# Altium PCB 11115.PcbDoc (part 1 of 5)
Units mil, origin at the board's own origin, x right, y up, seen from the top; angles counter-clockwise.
Board outline 4800 x 3500.1 mil, 4 copper layers (Top Layer, Layer 2, Layer 3, Bottom Layer), stack 61.6 mil thick; 316 components, 224 nets, 954 pads, 623 vias.
Unrouted connection lines stored in the file: 268.
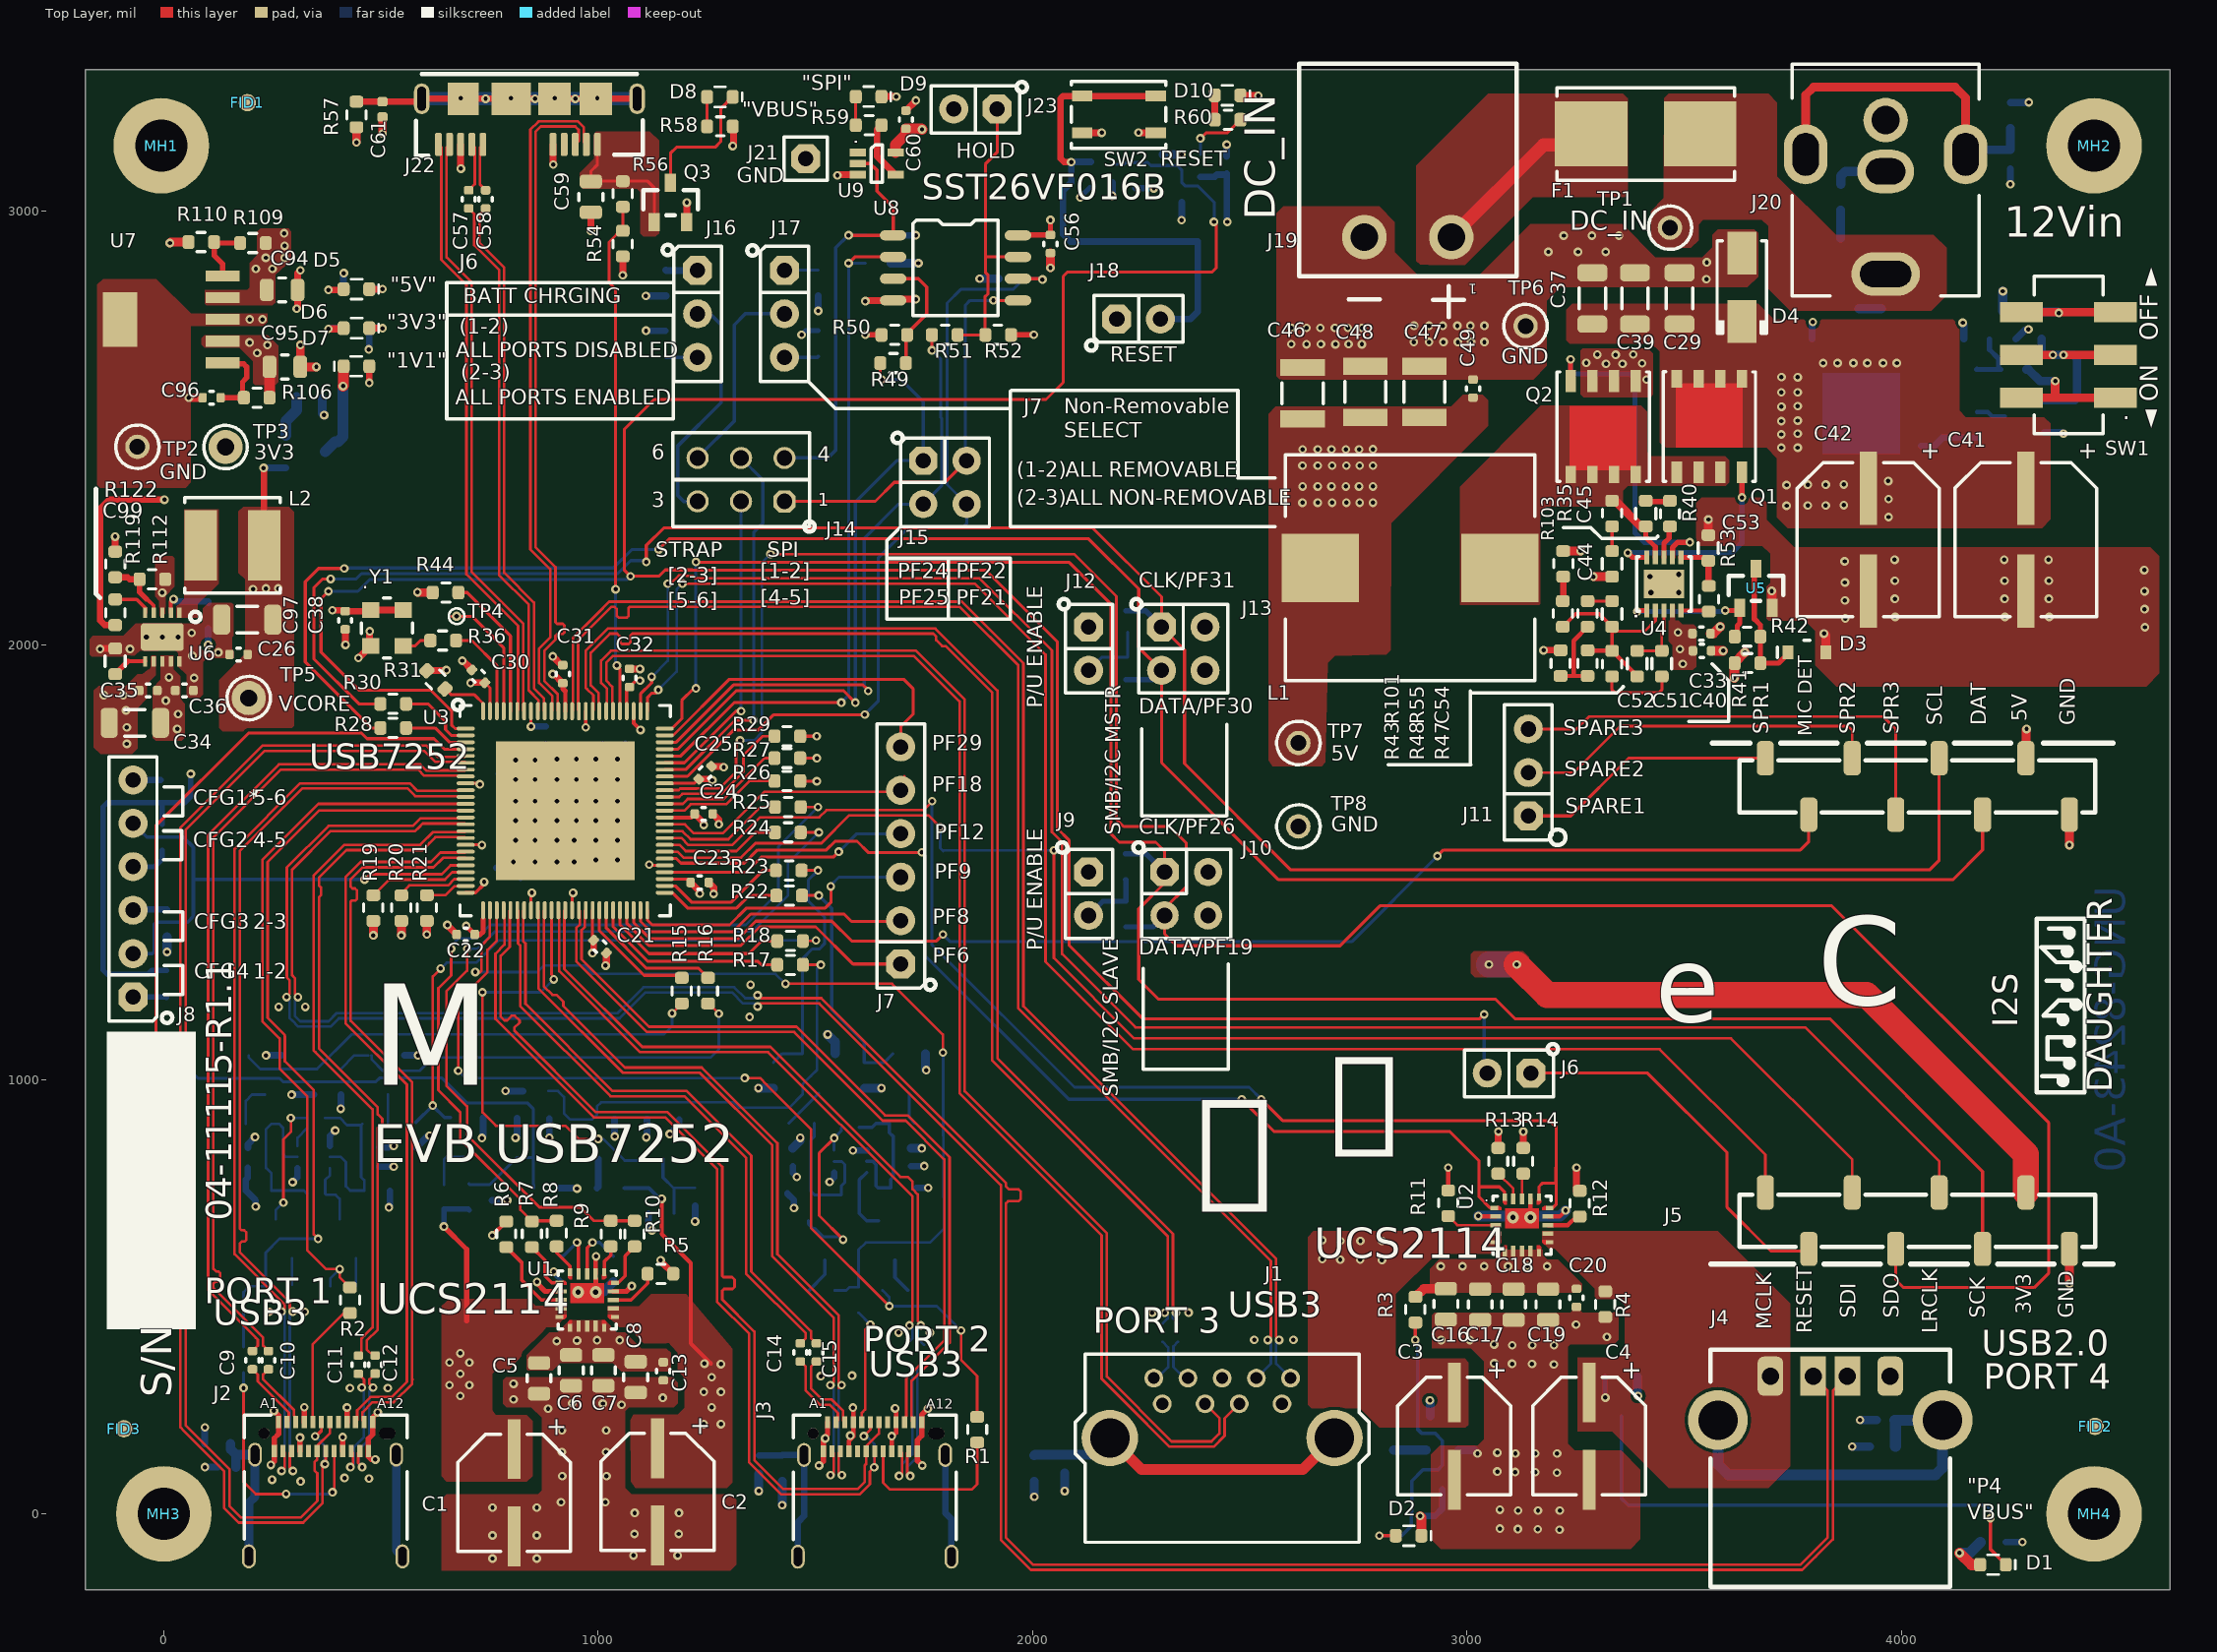
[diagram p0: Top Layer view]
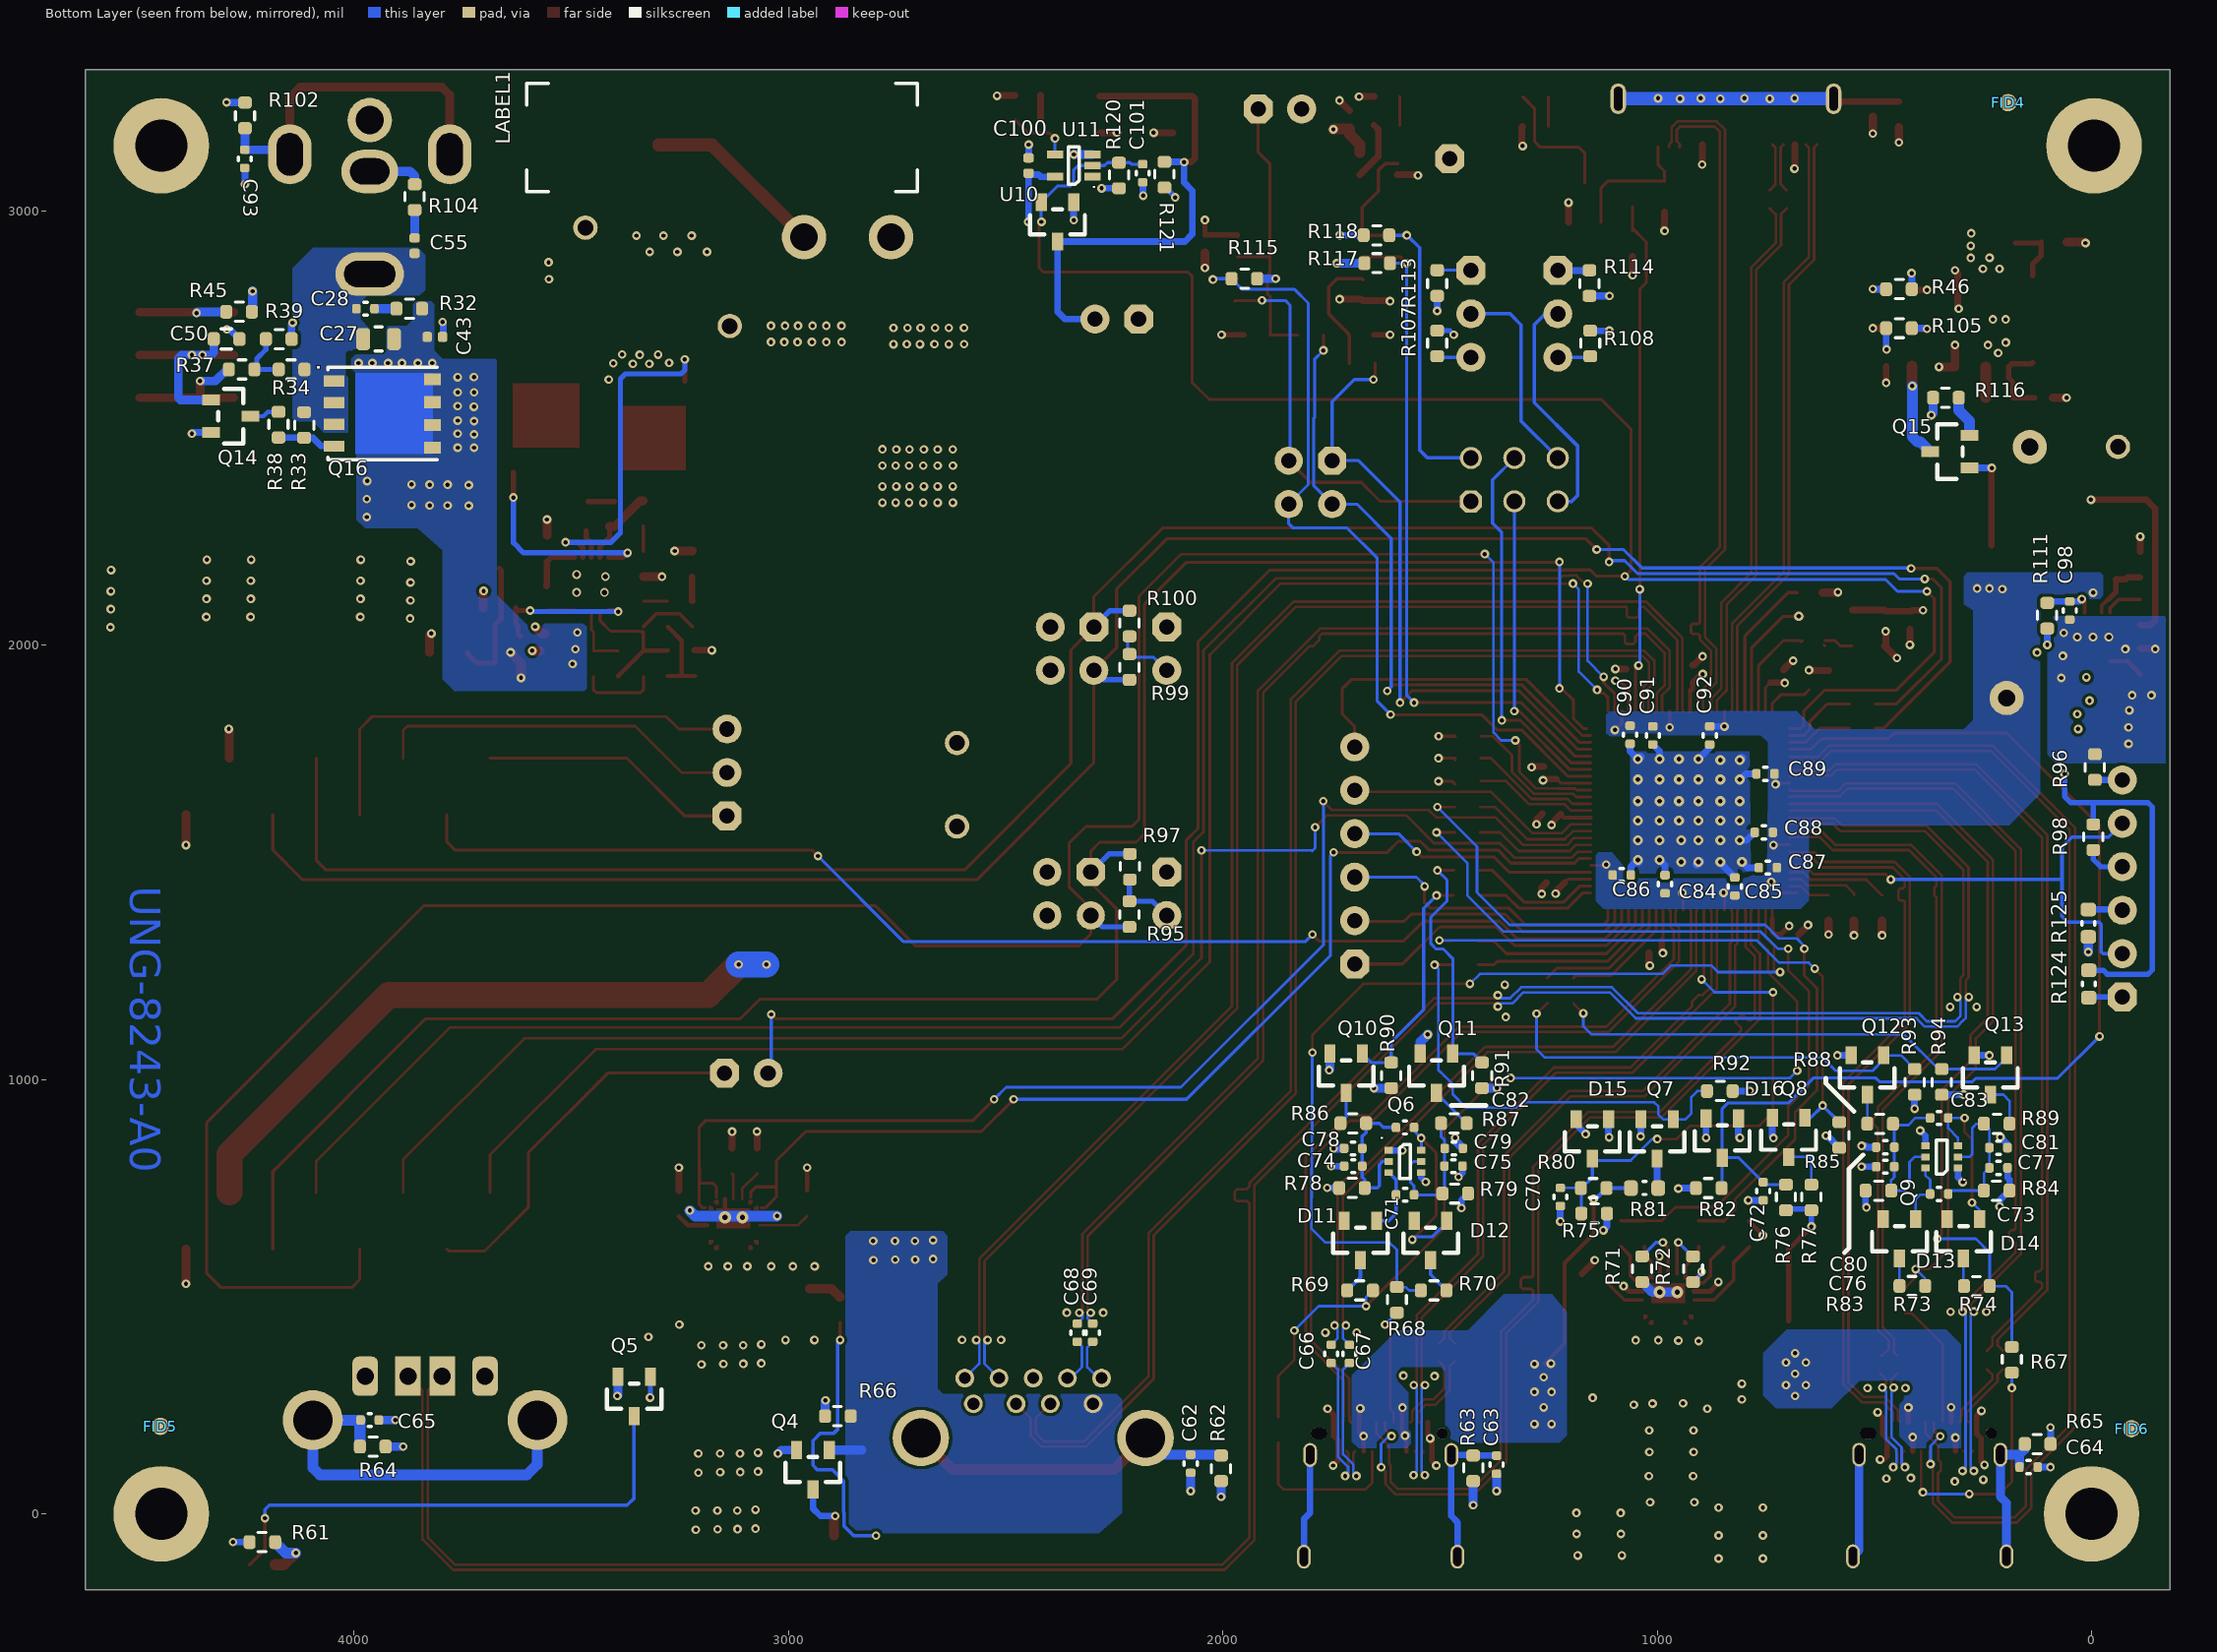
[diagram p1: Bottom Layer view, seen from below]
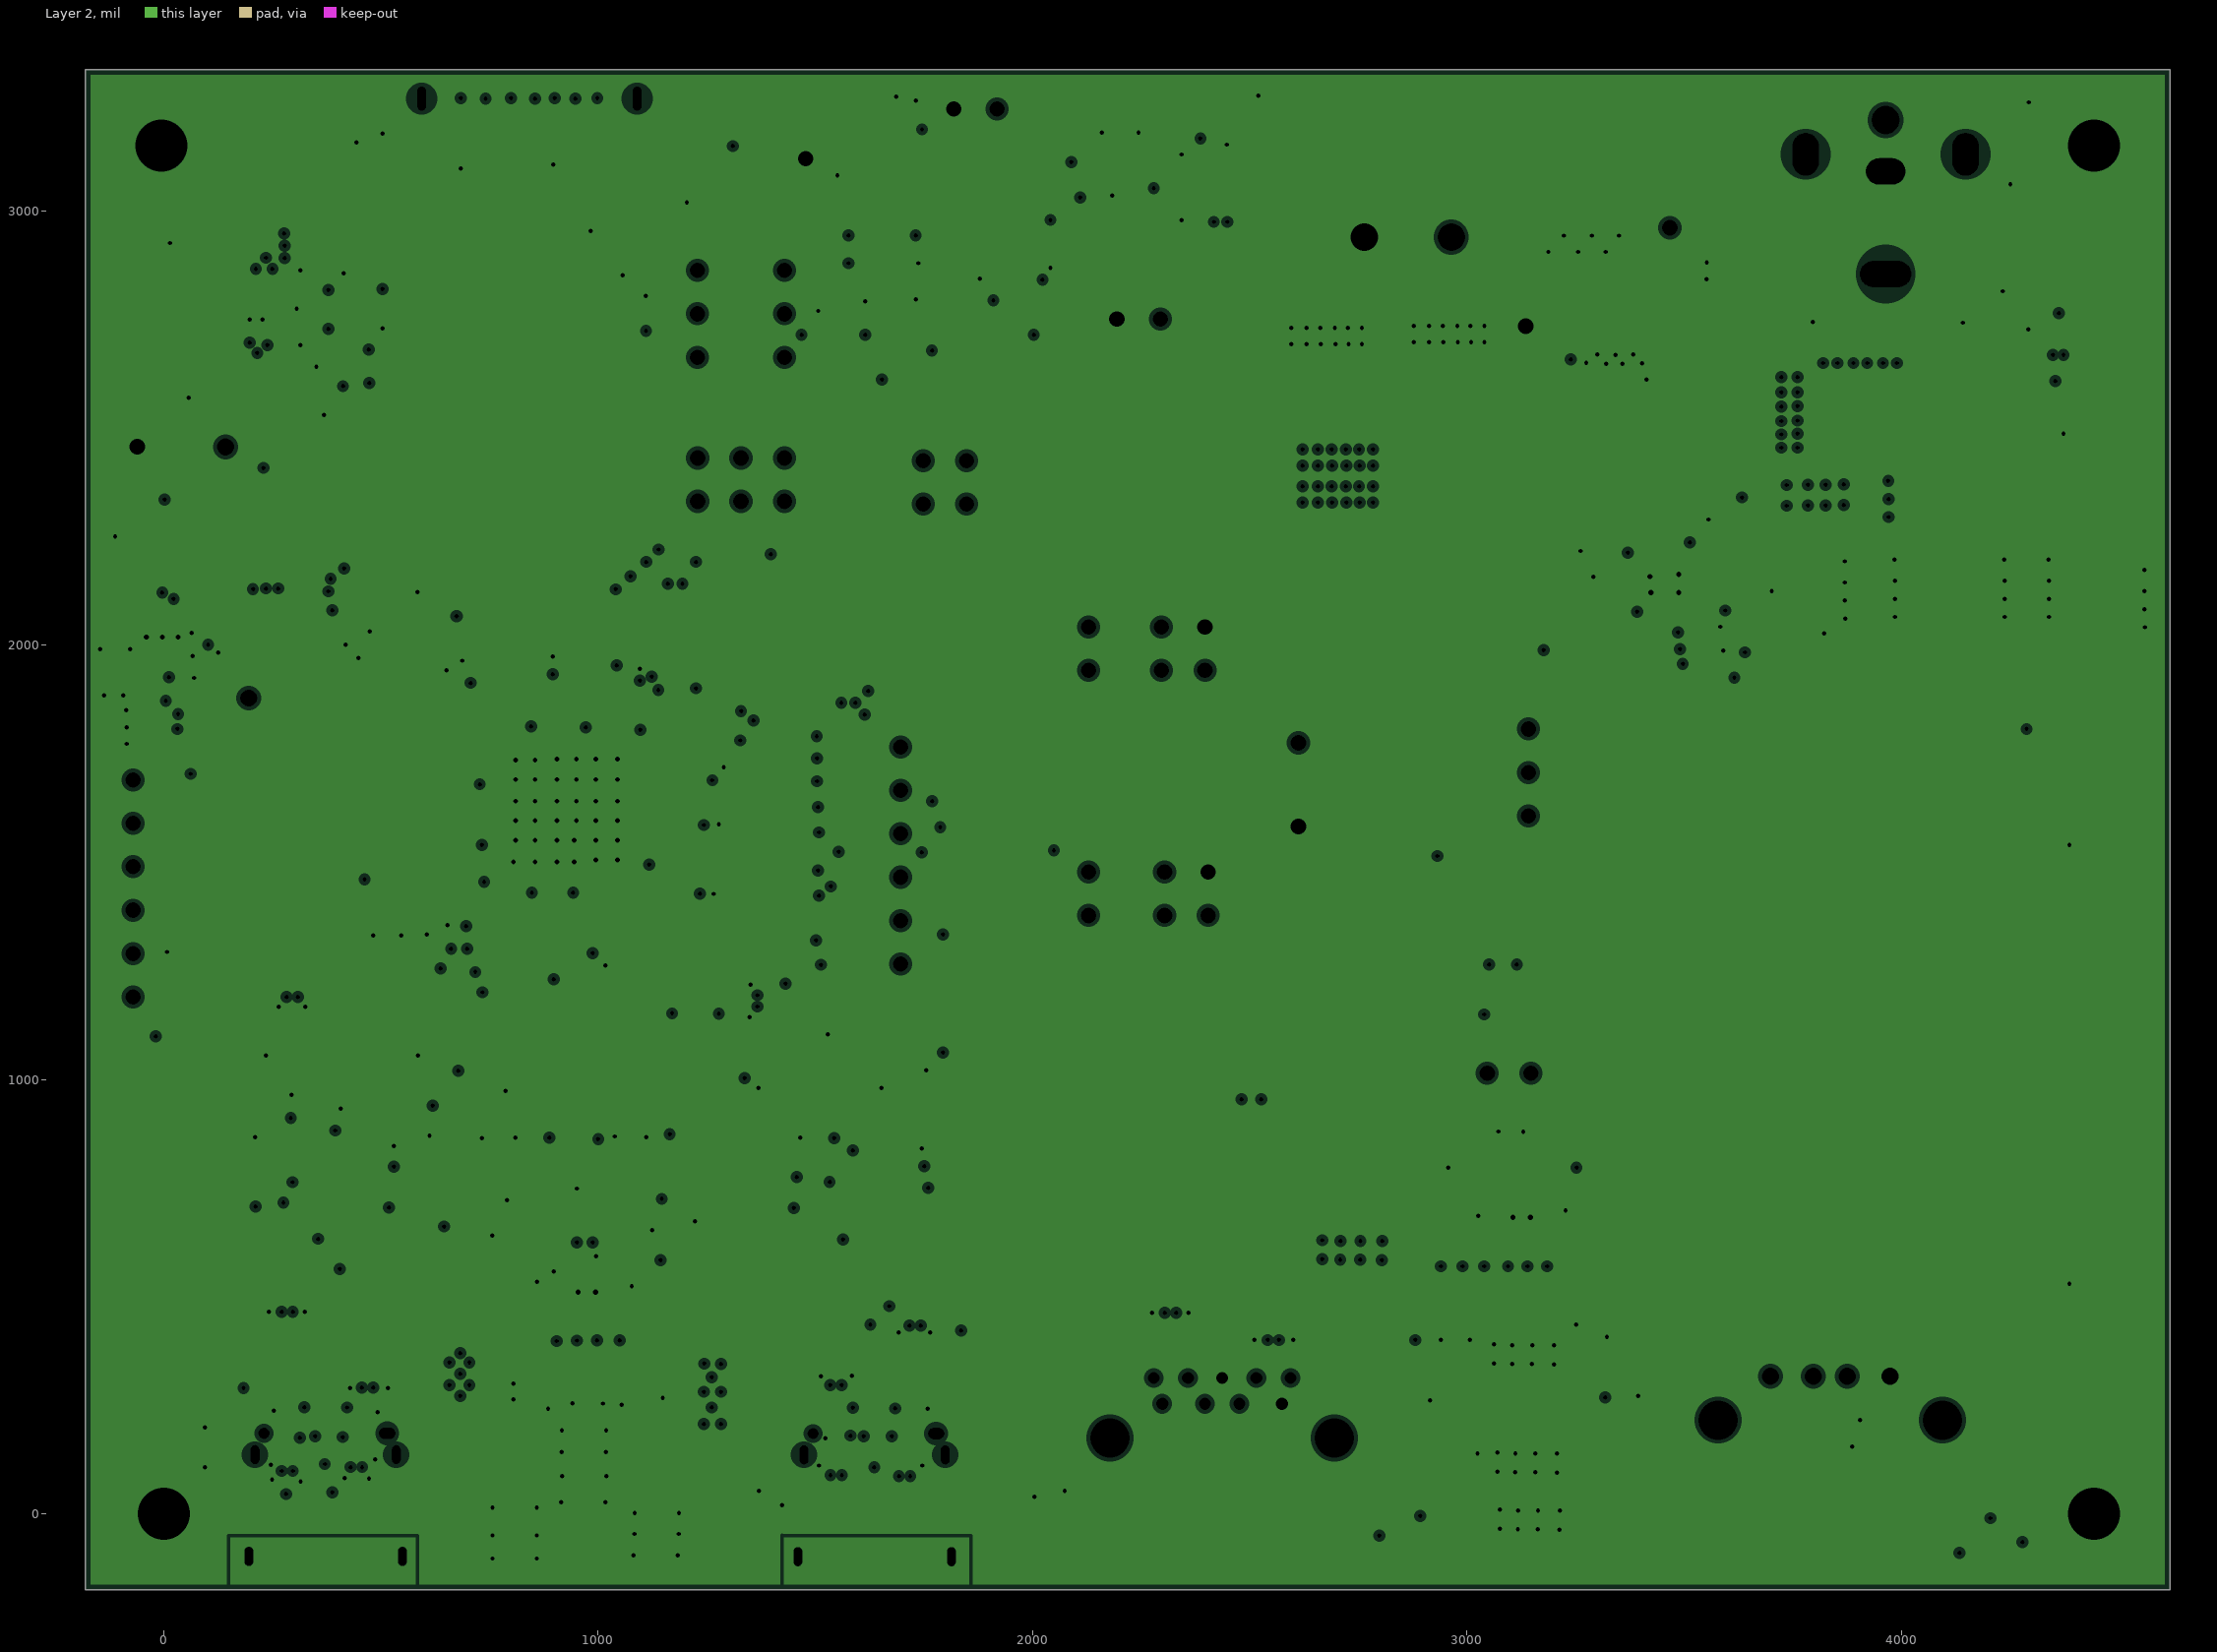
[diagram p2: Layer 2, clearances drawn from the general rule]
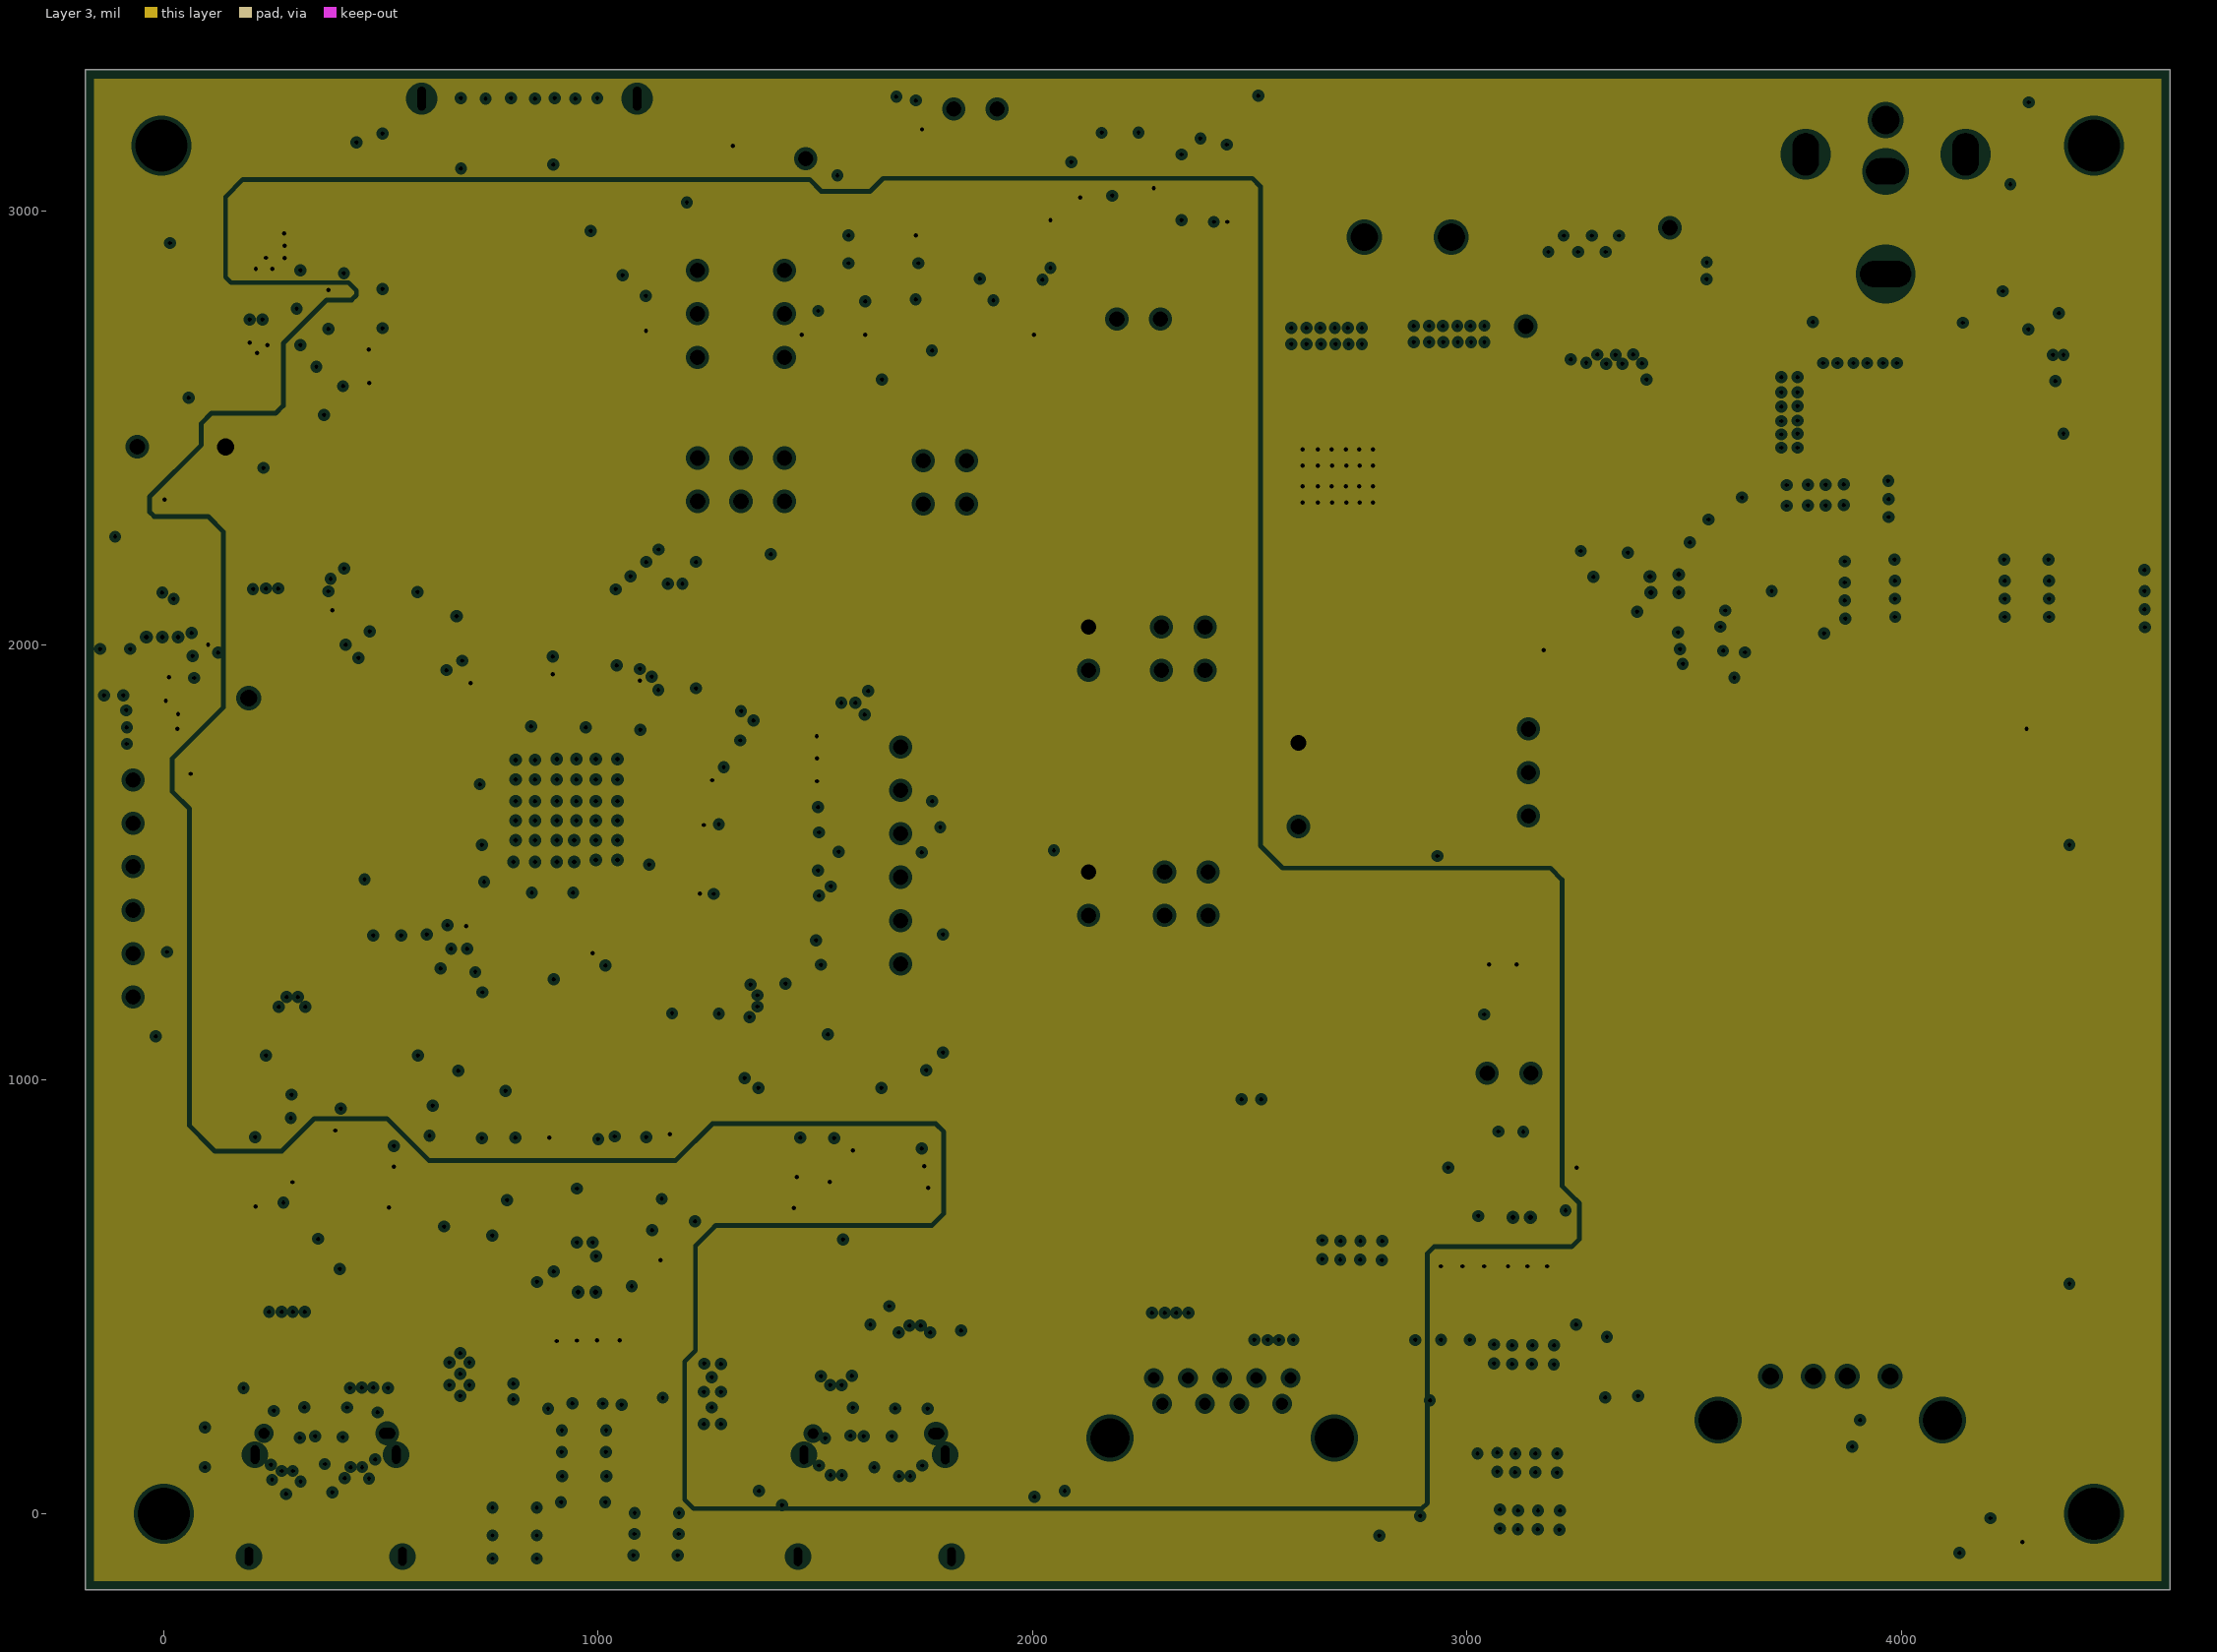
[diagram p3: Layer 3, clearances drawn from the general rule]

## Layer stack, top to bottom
Top Solder: solder mask 0.4, Solder Resist, Dk 3.5
Top Layer: signal copper 1.4
Dielectric 1: prepreg 4.5, 370HR(1PLY 1080&1PLY 106), Dk 4.2
Layer 2: plane copper 1.4, net (Multiple Nets)
Dielectric 2: core 47, 370 HR, Dk 4.3
Layer 3: plane copper 1.4, net (Multiple Nets)
Dielectric 3: dielectric 4.5, 370HR(1PLY 1080&1PLY 106), Dk 4.8
Bottom Layer: signal copper 1.4
Bottom Solder: solder mask 0.394, Solder Resist, Dk 3.5

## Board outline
-180.85,-175 4619.15,-175 4619.15,3325 -180.85,3325 -180.85,3325.1

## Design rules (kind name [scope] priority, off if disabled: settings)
AcuteAngle [All] p1: minimum=7.50000000000000E+0001 checktracksonly=TRUE
Clearance [All] p1: gap=6 ignorepadtopadclearanceinfootprint=TRUE except(5: Track-SMDPad; 7: THPad-Poly Via-Poly; 8: Arc-Poly Track-Poly SMDPad-Poly Fill-Poly; 12: Poly-Poly)
ComponentClearance ComponentClearance_ignore [HasFootprint('NET_TIE_0.5mm')] p1: gap=0 collisioncheckmode=3 verticalgap=0 showdistances=FALSE
ComponentClearance [All] p2: gap=7.87 collisioncheckmode=3 verticalgap=7.87 showdistances=FALSE
DiffPairsRouting [All] p1: maxlimit=7 minlimit=6 mostfreqgap=7 toplayer_minwidth=6 toplayer_maxwidth=6 toplayer_prefwidth=6 bottomlayer_minwidth=6 bottomlayer_maxwidth=6 bottomlayer_prefwidth=6 maxuncoupledlength=500
FabricationTestPointUsage TestPointUsage [All] p1: valid=0 allowmultiple=FALSE
FabricationTestpoint Testpoint [All] p1: side=3 testpointundercomponent=TRUE minsize=40 maxsize=100 preferedsize=60 minholesize=0 maxholesize=40 preferedholesize=32 testpointgrid=1 allowsidetop=TRUE allowsidebottom=TRUE usegrid=TRUE gridtolerance=0.01
HoleSize [All] p1: absolutevalues=TRUE maxlimit=236.22 minlimit=8 maxpercent=80.000 minpercent=20.000
HoleToHoleClearance [All] p1: gap=11.81 allowstackedmicrovias=FALSE
MinimumAnnularRing [All] p1: minimumring=3.9
MinimumSolderMaskSliver [All] p1: minsoldermaskwidth=1
PlaneClearance PlaneClearance_pads [IsPad] p1: clearance=8
PlaneClearance PlaneClearance_drill [All] p2: clearance=9
PlaneConnect usbcon [(HasFootprint('CON_USB3.1-C_RCPT_SMD_TH_RA_ACON') or InNet('GND1') or InNet('GND2'))] p1: planeconnectstyle=Direct reliefexpansion=20 reliefentries=4 reliefconductorwidth=10 reliefairgap=10
PlaneConnect PlaneConnect_full [IsVia] p2: planeconnectstyle=Direct reliefexpansion=19.68 reliefentries=4 reliefconductorwidth=11.81 reliefairgap=11.81
PlaneConnect [All] p3: planeconnectstyle=Relief reliefexpansion=10 reliefentries=4 reliefconductorwidth=15 reliefairgap=10
PolygonConnect PolygonConnect_full [All vs IsVia or IsNamedPolygon('full')] p1: connectstyle=Direct reliefconductorwidth=0 reliefentries=4 polygonreliefangle="90 Angle" airgapwidth=10
PolygonConnect [All] p2: connectstyle=Relief reliefconductorwidth=12 reliefentries=4 polygonreliefangle="90 Angle" airgapwidth=10
RoutingCorners [All] p1: cornerstyle=45-Degree minsetback=98.43 maxsetback=98.43
RoutingVias [All] p1: holewidth=10 width=20 viastyle="Through Hole" minholewidth=8 minwidth=18 maxholewidth=12 maxwidth=25
SMDToCorner [All] p1: distance=10000
ShortCircuit [IsNet] p1: allowed=FALSE
SilkToSilkClearance [All] p1: silktosilkclearance=3
SilkToSolderMaskClearance SilkscreenOverComponentPads [IsPad] p1: minsilkscreentomaskgap=0.1 clearancetoexposedcopper=TRUE
SolderMaskExpansion SolderMaskExpansion_Component_Via [IsComponentVia] p1: expansion=2.95 istentingtop=FALSE soldermaskfromhole=TRUE
SolderMaskExpansion [All] p2: expansion=3.94 istentingtop=FALSE
UnRoutedNet [All] p1: checkbadconnections=TRUE
ViasUnderSMD [All] p1: allowed=FALSE
Width [All] p1: maxlimit=200 minlimit=6 preferedwidth=7
16 further rules are at their usual default settings.

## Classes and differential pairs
component class 11115-6-Voltage_Regulators: C26 C27 C28 C29 C33 C34 C35 C36 C37 C39 C40 C41 C42 C43 C44 C45 C46 C47 C48 C49 C50 C51 C52 C53 C54 C55 C93 C94 C95 C96 C97 C98 C99 D3 D4 D5 D6 D7 F1 FID1 FID2 FID3 FID4 FID5 FID6 J19 J20 J21 L1 L2 LABEL1 MH1 MH2 MH3 MH4 Q1 Q2 Q14 Q15 Q16 R32 R33 R34 R35 R37 R38 R39 R40 R41 R42 R43 R45 R46 R47 R48 R53 R55 R101 R102 R103 R104 R105 R106 R109 R110 R111 R112 R116 R119 R122 SW1 TP1 TP2 TP3 TP5 TP6 TP7 TP8 U4 U5 U6 U7
component class "11115-5-USB-A Downstream 3-4": C3 C4 C16 C17 C18 C19 C20 C62 C65 C68 C69 D1 D2 J1 J4 Q4 Q5 R3 R4 R11 R12 R13 R14 R61 R62 R64 R66 U2
component class "11115-4-USB-C Downstream 1-2": C1 C2 C5 C6 C7 C8 C9 C10 C11 C12 C13 C14 C15 C63 C64 C66 C67 C70 C71 C72 C73 C74 C75 C76 C77 C78 C79 C80 C81 C82 C83 D11 D12 D13 D14 D15 D16 J2 J3 Q6 Q7 Q8 Q9 Q10 Q11 Q12 Q13 R1 R2 R5 R6 R7 R8 R9 R10 R63 R65 R67 R68 R69 R70 R71 R72 R73 R74 R75 R76 R77 R78 R79 R80 R81 R82 R83 R84 R85 R86 R87 R88 R89 R90 R91 R92 R93 R94 U1
component class 11115-3-USB-B-Upstream: C56 C57 C58 C59 C60 C61 D8 D9 J5 J6 J11 J15 J22 J23 Q3 R49 R50 R51 R52 R54 R56 R57 R58 R59 R115 R117 R118 U8 U9
component class 11115-2-USB7252: C21 C22 C23 C24 C25 C30 C31 C32 C38 C84 C85 C86 C87 C88 C89 C90 C91 C92 C100 C101 D10 J7 J8 J9 J10 J12 J13 J14 J16 J17 J18 R15 R16 R17 R18 R19 R20 R21 R22 R23 R24 R25 R26 R27 R28 R29 R30 R31 R36 R44 R60 R95 R96 R97 R98 R99 R100 R107 R108 R113 R114 R120 R121 R124 R125 SW2 TP4 U3 U10 U11 Y1
net class USB3.: C_USB3DN_TX3_N C_USB3DN_TX3_P C_USB3DN_TXD1A_N C_USB3DN_TXD1A_P C_USB3DN_TXD1B_N C_USB3DN_TXD1B_P C_USB3DN_TXD2A_N C_USB3DN_TXD2A_P C_USB3DN_TXD2B_N C_USB3DN_TXD2B_P UP_N UP_P USB2UP_N USB2UP_P USB3DN_RX1A_N USB3DN_RX1A_P USB3DN_RX1B_N USB3DN_RX1B_P USB3DN_RX2A_N USB3DN_RX2A_P USB3DN_RX2B_N USB3DN_RX2B_P USB3DN_RX3_N USB3DN_RX3_P USB3DN_TX1A_N USB3DN_TX1A_P USB3DN_TX1B_N USB3DN_TX1B_P USB3DN_TX2A_N USB3DN_TX2A_P USB3DN_TX2B_N USB3DN_TX2B_P USB3DN_TX3_N USB3DN_TX3_P USB3UP_RX_N USB3UP_RX_P USB3UP_TX_N USB3UP_TX_P
net class USB2.: USB2DN1/PRT_DIS_1_N USB2DN1/PRT_DIS_1_P USB2DN2/PRT_DIS_2_N USB2DN2/PRT_DIS_2_P USB2DN3/PRT_DIS_3_N USB2DN3/PRT_DIS_3_P USB2DN4/PRT_DIS_4_N USB2DN4/PRT_DIS_4_P USB2UP_N USB2UP_P
net class Power: 3V3_BRD 5V_BRD 5VL DC_IN EARTH_P0 EARTH_P1 EARTH_P2 EARTH_P3 EARTH_P4 FB3V3 FBVCORE GND L5V LVCORE VBUS1 VBUS3 VBUS4 VBUS_0 VCORE VIN
differential pair UP: +UP_P -UP_N
differential pair USB3UP_TX: +USB3UP_TX_P -USB3UP_TX_N
differential pair USB3UP_RX: +USB3UP_RX_P -USB3UP_RX_N
differential pair USB2UP: +USB2UP_P -USB2UP_N
differential pair USB3DN_TX3: +USB3DN_TX3_P -USB3DN_TX3_N
differential pair USB3DN_TX2B: +USB3DN_TX2B_P -USB3DN_TX2B_N
differential pair USB3DN_TX2A: +USB3DN_TX2A_P -USB3DN_TX2A_N
differential pair USB3DN_TX1B: +USB3DN_TX1B_P -USB3DN_TX1B_N
differential pair USB3DN_TX1A: +USB3DN_TX1A_P -USB3DN_TX1A_N
differential pair USB3DN_RX3: +USB3DN_RX3_P -USB3DN_RX3_N
differential pair USB3DN_RX2B: +USB3DN_RX2B_P -USB3DN_RX2B_N
differential pair USB3DN_RX2A: +USB3DN_RX2A_P -USB3DN_RX2A_N
differential pair USB3DN_RX1B: +USB3DN_RX1B_P -USB3DN_RX1B_N
differential pair USB3DN_RX1A: +USB3DN_RX1A_P -USB3DN_RX1A_N
differential pair USB2DN4/PRT_DIS_4: +USB2DN4/PRT_DIS_4_P -USB2DN4/PRT_DIS_4_N
differential pair USB2DN3/PRT_DIS_3: +USB2DN3/PRT_DIS_3_P -USB2DN3/PRT_DIS_3_N
differential pair USB2DN2/PRT_DIS_2: +USB2DN2/PRT_DIS_2_P -USB2DN2/PRT_DIS_2_N
differential pair USB2DN1/PRT_DIS_1: +USB2DN1/PRT_DIS_1_P -USB2DN1/PRT_DIS_1_N
differential pair C_USB3DN_TXD2B: +C_USB3DN_TXD2B_P -C_USB3DN_TXD2B_N
differential pair C_USB3DN_TXD2A: +C_USB3DN_TXD2A_P -C_USB3DN_TXD2A_N
differential pair C_USB3DN_TXD1B: +C_USB3DN_TXD1B_P -C_USB3DN_TXD1B_N
differential pair C_USB3DN_TXD1A: +C_USB3DN_TXD1A_P -C_USB3DN_TXD1A_N
differential pair C_USB3DN_TX3: +C_USB3DN_TX3_P -C_USB3DN_TX3_N

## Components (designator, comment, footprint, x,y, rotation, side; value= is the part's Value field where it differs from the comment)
C1 "Capacitor POL" CAP_AL_D8 806.5,48.7 r270 top value=150uF
C2 "Capacitor POL" CAP_AL_D8 1136.79,50.61 r270 top value=150uF
C3 "Capacitor POL" CAP_AL_D8 2970.85,179.08 r270 top value=150uF
C4 "Capacitor POL" CAP_AL_D8 3281.65,179.08 r270 top value=150uF
C5 "Capacitor NP" CAP_C_0805 863.94,312.07 r90 top value=47uF
C6 "Capacitor NP" CAP_C_0805 937.82,330.41 r270 top value=47uF
C7 "Capacitor NP" CAP_C_0805 1012.13,330.41 r90 top value=47uF
C8 "Capacitor NP" CAP_C_0805 1086.42,314.91 r270 top value=47uF
C9 "Capacitor NP" CAP_C_0402#1 204.2,353.98 r270 top value=0.1uF
C10 "Capacitor NP" CAP_C_0402#1 241.01,353.98 r270 top value=0.1uF
C11 "Capacitor NP" CAP_C_0402#1 447.94,343.44 r270 top value=0.1uF
C12 "Capacitor NP" CAP_C_0402#1 486.52,343.82 r270 top value=0.1uF
C13 "Capacitor NP" CAP_C_0402#1 1149.97,328.33 r90 top value=0.1uF
C14 "Capacitor NP" CAP_C_0402#1 1465.53,371.78 r270 top value=0.1uF
C15 "Capacitor NP" CAP_C_0402#1 1502.38,371.78 r270 top value=0.1uF
C16 "Capacitor NP" CAP_C_0805 2951.65,482.96 r90 top value=47uF
C17 "Capacitor NP" CAP_C_0805 3030.65,481.96 r270 top value=47uF
C18 "Capacitor NP" CAP_C_0805 3107.65,481.96 r270 top value=47uF
C19 "Capacitor NP" CAP_C_0805 3186.89,481.96 r90 top value=47uF
C20 "Capacitor NP" CAP_C_0402#1 3252.3,497.45 r90 top value=0.1uF
C21 "Capacitor NP" CAP_C_0402#1 1004.27,1306.11 r315 top value=0.1uF
C22 "Capacitor NP" CAP_C_0402#1 695.05,1334 r180 top value=0.1uF
C23 "Capacitor NP" CAP_C_0402#1 1233.92,1453.7 r0 top value=0.1uF
C24 "Capacitor NP" CAP_C_0402#1 1243.17,1611.74 r0 top value=0.1uF
C25 "Capacitor NP" CAP_C_0402#1 1246.37,1706.56 r45 top value=0.1uF
C26 "Capacitor NP" CAP_C_0402#1 172.22,1978.81 r0 top value=0.1uF
C27 "Capacitor NP" CAP_C_0805 3943.83,2705 r0 bottom value=10uF
C28 "Capacitor NP" CAP_C_0402#1 3974.15,2775 r180 bottom value=0.1uF
C29 "Capacitor NP" CAP_C_1206 3489.75,2798.52 r270 top value=10uF
C30 "Capacitor NP" CAP_C_0402#1 724.43,1928.55 r135 top value=0.1uF
C31 "Capacitor NP" CAP_C_0402#1 918.59,1933.5 r90 top value=0.1uF
C32 "Capacitor NP" CAP_C_0402#1 1072.15,1924.78 r90 top value=0.1uF
C33 "Capacitor NP" CAP_C_0402#1 3540.32,2026.88 r180 top value=0.1uF
C34 "Capacitor NP" CAP_C_1206 -66.55,1821.36 r0 top value=22uF
C35 "Capacitor NP" CAP_C_0402#1 -35.64,1895.97 r0 top value=0.1uF
C36 "Capacitor NP" CAP_C_0402#1 47.23,1895.97 r180 top value=0.1uF
C37 "Capacitor NP" CAP_C_1206 3288.82,2798.52 r270 top value=10uF
C38 "Capacitor NP" CAP_C_0402#1 417.75,2057.58 r90 top value=0.1uF
C39 "Capacitor NP" CAP_C_1206 3387,2798.52 r270 top value=10uF
C40 "Capacitor NP" CAP_C_0402#1 3541.32,1987.21 r180 top value=0.1uF
C41 "Capacitor POL" CAP_AL_F 4286.71,2243.11 r270 top value=47uF
C42 "Capacitor POL" CAP_AL_F 3924.15,2243.11 r270 top value=47uF
C43 "Capacitor NP" CAP_C_0402#2 3814,2710 r0 bottom value=0.1uF
C44 "Capacitor NP" CAP_C_0603 3334.21,2187.42 r270 top value=0.33uF
C45 "Capacitor NP" CAP_C_0603 3411.8,2303.24 r270 top value=0.33uF
C46 "Capacitor NP" CAP_C_1210 2622.02,2580.35 r270 top value=100uF
C47 "Capacitor NP" CAP_C_1210 2902.02,2583.3 r270 top value=100uF
C48 "Capacitor NP" CAP_C_1210 2766.2,2583.3 r270 top value=100uF
C49 "Capacitor NP" CAP_C_0402#1 3014.15,2590.96 r270 top value=0.1uF
C50 "Capacitor NP" CAP_C_0603 4293.72,2705 r0 bottom value=1uF
C51 "Capacitor NP" CAP_C_0603 3448.88,1957.68 r270 top value=3900pF
C52 "Capacitor NP" CAP_C_0603 3392.15,1957.68 r270 top value=33pF
C53 "Capacitor NP" CAP_C_0603 3556.07,2224.03 r270 top value=4.7uF
C54 "Capacitor NP" CAP_C_0603 3334.21,2072.16 r90 top value=680pF
C55 "Capacitor NP" CAP_C_0402#2 3860.8,2920.01 r270 bottom value=0.1uF
C56 "Capacitor NP" CAP_C_0402#1 2041.31,2923.95 r90 top value=0.1uF
C57 "Capacitor NP" CAP_C_0402#1 702,3026.78 r270 top value=0.1uF
C58 "Capacitor NP" CAP_C_0402#1 741,3026.65 r270 top value=0.1uF
C59 "Capacitor NP" CAP_C_0805 983.29,3032.36 r90 top value=10uF
C60 "Capacitor NP" CAP_C_0402#1 1708.58,3210 r90 top value=0.1uF
C61 "Capacitor NP" CAP_C_0402#2 503.5,3233.94 r90 top value=0.1uF
C62 "Capacitor NP" CAP_C_0402#1 2074.15,115.42 r90 bottom value=0.1uF
C63 "Capacitor NP" CAP_C_0402#1 1369.87,113.23 r90 bottom value=0.1uF
C64 "Capacitor NP" CAP_C_0402#1 145.02,107.76 r0 bottom value=0.1uF
C65 "Capacitor NP" CAP_C_0402#1 3964.15,216 r0 bottom value=0.1uF
C66 "Capacitor NP" CAP_C_0402#1 1750.73,368.37 r270 bottom value=0.1uF
C67 "Capacitor NP" CAP_C_0402#1 1708.65,368.23 r270 bottom value=0.1uF
C68 "Capacitor NP" CAP_C_0402#1 2335.17,417.36 r270 bottom value=0.1uF
C69 "Capacitor NP" CAP_C_0402#1 2299.72,417.36 r270 bottom value=0.1uF
C70 "Capacitor NP" CAP_C_0402#1 1223.18,729.67 r270 bottom value=0.1uF
C71 "Capacitor NP" CAP_C_0402#1 1580.75,734.66 r0 bottom value=0.1uF
C72 "Capacitor NP" CAP_C_0402#1 755.95,742.87 r270 bottom value=0.1uF
C73 "Capacitor NP" CAP_C_0402#1 350.95,736.73 r0 bottom value=0.1uF
C74 "Capacitor NP" CAP_C_0402#1 1699.88,800.8 r0 bottom value=0.1uF
C75 "Capacitor NP" CAP_C_0402#1 1469.18,800.8 r180 bottom value=0.1uF
C76 "Capacitor NP" CAP_C_0402#1 475.15,799.26 r0 bottom value=0.1uF
C77 "Capacitor NP" CAP_C_0402#1 214.51,796.73 r180 bottom value=0.1uF
C78 "Capacitor NP" CAP_C_0402#1 1699.88,841.57 r180 bottom value=0.1uF
C79 "Capacitor NP" CAP_C_0402#1 1468.39,841.57 r0 bottom value=0.1uF
C80 "Capacitor NP" CAP_C_0402#1 475.15,844.26 r180 bottom value=0.1uF
C81 "Capacitor NP" CAP_C_0402#1 214.51,843.13 r0 bottom value=0.1uF
C82 "Capacitor NP" CAP_C_0402#1 1580.75,889.73 r180 bottom value=0.1uF
C83 "Capacitor NP" CAP_C_0402#1 350.95,911.73 r180 bottom value=0.1uF
C84 "Capacitor NP" CAP_C_0402#1 982.05,1449.75 r90 bottom value=0.1uF
C85 "Capacitor NP" CAP_C_0402#1 821.41,1444.63 r90 bottom value=0.1uF
C86 "Capacitor NP" CAP_C_0402#1 1081.66,1470.96 r180 bottom value=0.1uF
C87 "Capacitor NP" CAP_C_0402#1 745.3,1487.89 r0 bottom value=0.1uF
C88 "Capacitor NP" CAP_C_0402#1 754.77,1569.14 r0 bottom value=0.1uF
C89 "Capacitor NP" CAP_C_0402#1 750.95,1703.98 r0 bottom value=0.1uF
C90 "Capacitor NP" CAP_C_0402#1 1062.45,1793.88 r270 bottom value=0.1uF
C91 "Capacitor NP" CAP_C_0402#1 1010.19,1792.36 r270 bottom value=0.1uF
C92 "Capacitor NP" CAP_C_0402#1 879.13,1792.36 r270 bottom value=0.1uF
C93 "Capacitor NP" CAP_C_0402#1 4252,3120 r270 bottom value=0.1uF
C94 "Capacitor NP" CAP_C_0805 272.51,2818.13 r180 top value=10uF
C95 "Capacitor NP" CAP_C_0805 278.84,2640.99 r180 top value=10uF
C96 "Capacitor NP" CAP_C_0402#1 110.1,2570 r0 top value=0.1uF
C97 "Capacitor NP" CAP_C_1206 192.23,2059.1 r0 top value=22uF
C98 "Capacitor NP" CAP_C_0402#1 50.23,2079.97 r90 bottom value=2.2uF
C99 "Capacitor NP" CAP_C_0603 -111.77,1963.06 r270 top value=470pF
C100 "Capacitor NP" CAP_C_0402#2 2447.45,3104.41 r90 bottom value=0.1uF
C101 "Capacitor NP" CAP_C_0402#1 2184.47,3086.69 r90 bottom value=0.1uF
D1 "LED_green" LED_0603_GREEN 4211.28,-117 r0 top value=GREEN
D2 "LED_green" LED_0603_GREEN 2865.9,-50.27 r0 top value=GREEN
D3 "Diode Zener" SOD-323 3782.85,1983.66 r180 top value=MM3Z5V1ST1G
D4 "Diode TVS Unidirectional" DO-214AC_SMA 3633.23,2824.57 r270 top value="15.3VWM 32.3VC"
D5 "LED_green" LED_0603_GREEN 443.5,2820 r0 top value=GREEN
D6 "LED_green" LED_0603_GREEN 443.5,2730 r0 top value=GREEN
D7 "LED_green" LED_0603_GREEN 443.5,2642.37 r180 top value=GREEN
D8 "LED_green" LED_0603_GREEN 1280.35,3262.64 r0 top value=GREEN
D9 "LED_blue" LED_0603_BLUE 1622.74,3263.18 r0 top value=BLUE
D10 "LED_red" LED_0603_RED 2449.15,3266.25 r0 top value=RED
D11 "Diode SBR160S23" SOT-23-3_REVERSED 1683.35,629.58 r0 bottom value=SBR160S23
D12 "Diode SBR160S23" SOT-23-3_REVERSED 1521.7,629.58 r0 bottom value=SBR160S23
D13 "Diode SBR160S23" SOT-23-3_REVERSED 442.34,633.31 r0 bottom value=SBR160S23
D14 "Diode SBR160S23" SOT-23-3_REVERSED 294.93,633.31 r0 bottom value=SBR160S23
D15 "Diode Dual AK" SOT-23-3 1149.39,863.17 r0 bottom value=BAV99
D16 "Diode Dual AK" SOT-23-3 850.44,865.31 r0 bottom value=BAV99
F1 "FUSE 2 pin" FUSEHOLDER_LITTLEFUSE_155900 3411.8,3177.24 r180 top value="FAST 10A"
FID1 "FIDUCIAL" FIDUCIAL 192.39,3249.35 r0 top
FID2 "FIDUCIAL" FIDUCIAL 4446.2,201.51 r0 top
FID3 "FIDUCIAL" FIDUCIAL -92,196.07 r0 top
FID4 "FIDUCIAL" FIDUCIAL 192.39,3249.4 r180 bottom
FID5 "FIDUCIAL" FIDUCIAL 4446.2,201.56 r180 bottom
FID6 "FIDUCIAL" FIDUCIAL -92,196.12 r180 bottom
J1 "CON USB3.0 A-B" CON_USB3.0-A_RCPT_TH_RA_WE_692121030100 2436.65,174.73 r0 top value="USB3.0 STD-A FEMALE"
J2 "USBC_Receptacle_SMD_RA" CON_USB3.1-C_RCPT_SMD_RA_ACP_12401610E4#2A 372.65,14.73 r0 top locked value="USB3.1 TYPE-C FEMALE"
J3 "USBC_Receptacle_SMD_RA" CON_USB3.1-C_RCPT_SMD_RA_ACP_12401610E4#2A 1636.65,14.08 r0 top value="USB3.1 TYPE-C FEMALE"
J4 "CON USB2.0 A-B" CON_USB2.0-A_TH_RA_FCI_87520-0010BLF 3836.65,216 r0 top value="USB2.0 STD-A FEMALE"
J5 "SOCKET I2S HOST" SOCKET_I2S_F_2.54_2x8_V_25.4x21_SMD 4037.22,1175 r90 top value="I2S HOST"
J6 "Header 1x2" HDR_M_2.54_1x2 3097.02,1015 r180 top value="HDR-2.54 Male 1x2"
J7 "Header 1x6" HDR_M_2.54_1x6 1696.66,1515.99 r90 top value="HDR-2.54 Male 1x6"
J8 "Header 1x6" HDR_M_2.54_1x6 -70.85,1440 r90 top value="HDR-2.54 Male 1x6"
J9 "Header 1x2" HDR_M_2.54_1x2 2129.15,1427.79 r270 top value="HDR-2.54 Male 1x2"
J10 "Header 2x2" HDR_M_2.54_2x2#1 2354.15,1427.79 r270 top value="HDR-2.54 Male 2x2"
J11 "Header 1x3" HDR_M_2.54_1x3 3141.41,1707.09 r90 top value="HDR-2.54 Male 1x3"
J12 "Header 1x2" HDR_M_2.54_1x2 2129.15,1992.28 r270 top value="HDR-2.54 Male 1x2"
J13 "Header 2x2" HDR_M_2.54_2x2#2 2347.14,1992.28 r270 top value="HDR-2.54 Male 2x2"
J14 "Header 3X2" CON_HDR_2.54_3X2 1328.96,2381.29 r90 top value="HDR-2.54 MALE 3X2"
J15 "Header 2x2" HDR_M_2.54_2x2#1 1798.52,2375 r270 top value="HDR-2.54 Male 2x2"
J16 "Header 1x3" HDR_M_2.54_1x3 1228.96,2763.13 r270 top value="HDR-2.54 Male 1x3"
J17 "Header 1x3" HDR_M_2.54_1x3 1428.96,2763.13 r270 top value="HDR-2.54 Male 1x3"
J18 "Header 1x2" HDR_M_2.54_1x2 2244.15,2750.87 r0 top value="HDR-2.54 Male 1x2"
J19 "Header 1x2" CON_TERMINAL_5.08_1x2_TH_RA_OST_OSTOQ025451 2864.15,2939.69 r180 top value="TERMINAL 1X2"
J20 "CON JACK 2C SHLD" CON_JACK_POWER_TH_RA_CUI_PJ-063BH 3964.15,3031.89 r90 top value="POWER 2.5mm"
J21 "Header 1x1" HDR_M_2.54_1x1 1477.85,3120.28 r0 top value="HDR-2.54 Male 1x1"
J22 "CON USB3.0 Micro B" CON_USB3.0-B_RCPT_SMD_RA_HIR_ZX360D-B-10P 856.15,3268.18 r180 top value="USB3.0 MICRO-B FEMALE"
J23 "Header 1x2" HDR_M_2.54_1x2 1868.69,3234.8 r180 top value="HDR-2.54 Male 1x2"
L1 "Inductor" IND_WE_7443551200_L12.8W12.8H6.2 2869.15,2178.28 r180 top value=2uH
L2 "Inductor" IND_MUR_LQH5B_L5W5H2 158.23,2229.97 r0 top value=1.5uH
LABEL1 "LABEL_Need_Help_Small" LABEL_Need_Help_Small 3153,3169 r0 bottom value="LABEL Need Help Small"
MH1 "MTHOLE 4-40 120DL 220PAD" MTHOLE_4-40#1 -5.85,3150 r0 top
MH2 "MTHOLE 4-40 120DL 220PAD" MTHOLE_4-40#1 4444.15,3150 r0 top
MH3 "MTHOLE 4-40 120DL 220PAD" MTHOLE_4-40#2 -5.85,0 r0 top
MH4 "MTHOLE 4-40 120DL 220PAD" MTHOLE_4-40#1 4444.15,0 r0 top
Q1 "Transistor MOS-N SSSGDDDD" Power56-8_5x6 3558.23,2503.36 r0 top value=SiRA24DP
Q2 "Transistor MOS-N SSSGDDDD" Power56-8_5x6 3313.82,2503.32 r180 top value=SiRA12BDP
Q3 "Transistor MOS-N GSD" SOT-23-3 1166.57,3019.32 r0 top value=2N7002-7-F
Q4 "Transistor MOS-N GSD" SOT-23-3 2943.85,101.79 r0 bottom value=2N7002-7-F
Q5 "Transistor MOS-N GSD" SOT-23-3 3355.4,270.45 r0 bottom value=2N7002-7-F
Q6 "Transistor MOS-P+P Dual SGDSGD" SC-88-6 1580.75,811.37 r270 bottom value=FDG6316P
Q7 "" SOT-23-3 1000.23,863.17 r0 bottom value=2N7002-7-F
Q8 "" SOT-23-3 697.38,867.01 r0 bottom value=2N7002-7-F
Q9 "Transistor MOS-P+P Dual SGDSGD" SC-88-6 345.15,821.73 r90 bottom value=FDG6316P
Q10 "" SOT-23-3 1716.34,1014.39 r0 bottom value=2N7002-7-F
Q11 "" SOT-23-3 1508.16,1014.39 r0 bottom value=2N7002-7-F
Q12 "" SOT-23-3 516.39,1010.49 r0 bottom value=2N7002-7-F
Q13 "" SOT-23-3 233.08,1010.49 r0 bottom value=2N7002-7-F
Q14 "Transistor MOS-N GSD" SOT-23-3 4283.87,2527.4 r270 bottom value=2N7002-7-F
Q15 "Transistor NPN BEC" SOT-23-3 326.38,2445.74 r90 bottom value=MMBT3904
Q16 "Transistor MOS-P SSSGDDDD" PG-TDSON-8_4.7x6.5 3934.82,2533.47 r270 bottom value="BSC060P03NS3E G"
R1 "0R" RES_C_0603#1 1872.65,193.68 r270 top
R2 "0R" RES_C_0603#1 428.68,491.75 r270 top
R3 "Resistor" RES_C_0603#1 2881.65,470 r270 top value=2.2k
R4 "Resistor" RES_C_0603#1 3318.76,482.92 r90 top value=1k
R5 "Resistor" RES_C_0603#1 1143.44,552.74 r180 top value=10k
R6 "Resistor" RES_C_0603#1 788.44,643.86 r270 top value=33k
R7 "Resistor" RES_C_0603#1 847.44,643.86 r270 top value=0R
R8 "Resistor" RES_C_0603#1 904.51,645.33 r270 top value=0R
R9 "Resistor" RES_C_0603#1 1029.08,645.33 r90 top value=0R
R10 "Resistor" RES_C_0603#1 1083.89,645.33 r90 top value=0R
R11 "Resistor" RES_C_0603#1 2957.13,715.2 r270 top value=33k
R12 "Resistor" RES_C_0603#1 3259.8,714.21 r270 top value=10k
R13 "100k" RES_C_0603#1 3072.22,812.96 r90 top
R14 "100k" RES_C_0603#1 3129.8,812.96 r90 top
R15 "0R" RES_C_0603#1 1192.54,1204.73 r90 top
R16 "0R" RES_C_0603#1 1253.06,1204.73 r90 top
R17 "0R" RES_C_0603#1 1441.75,1264.24 r180 top
R18 "0R" RES_C_0603#1 1441.75,1319.11 r180 top
R19 "Resistor" RES_C_0603#1 482.45,1394.86 r270 top value=200k
R20 "Resistor" RES_C_0603#1 546.95,1394.86 r270 top value=200k
R21 "Resistor" RES_C_0603#1 605.76,1394.86 r270 top value=10k
R22 "0R" RES_C_0603#1 1439.71,1423.77 r180 top
R23 "0R" RES_C_0603#1 1438.86,1481.64 r180 top
R24 "0R" RES_C_0603#1 1436.79,1569.14 r180 top
R25 "0R" RES_C_0603#1 1436.79,1627.49 r180 top
R26 "Resistor" RES_C_0603#1 1435.65,1687.42 r0 top value=10k
R27 "Resistor" RES_C_0603#1 1435.65,1740.16 r0 top value=10k
R28 "0R" RES_C_0603#1 528.3,1809.63 r0 top
R29 "Resistor" RES_C_0603#1 1435.65,1790.55 r0 top value=10k
R30 "0R" RES_C_0603#1 528.3,1865 r0 top
R31 "Resistor" RES_C_0603#1 626.51,1920.44 r315 top value=12k
R32 "20R" RES_C_0603#1 3873.2,2775 r0 bottom
R33 "Resistor" RES_C_0603#1 4115.13,2507.28 r90 bottom value=10k
R34 "Resistor" RES_C_0603#1 4144.15,2635 r180 bottom value=10k
R35 "Resistor" RES_C_0603#1 3334.21,2303.24 r270 top value=0R
R36 "Resistor" RES_C_0603#1 643.15,2010.83 r0 top value=0R
R37 "Resistor" RES_C_0603#1 4259.15,2635 r0 bottom value=470k
R38 "Resistor" RES_C_0603#1 4174.19,2507.72 r270 bottom value=2.2k
R39 "Resistor" RES_C_0603#1 4173.68,2705 r0 bottom value=20k
R40 "Resistor" RES_C_0603#1 3467.48,2303.24 r90 top value=0R
R41 "Resistor" RES_C_0603#1 3646.16,1958.86 r180 top value=10k
R42 "Resistor" RES_C_0603#1 3646.16,2019.8 r0 top value=10k
R43 "Resistor" RES_C_0603#1 3215.84,1958.86 r90 top value=0R
R44 "Resistor" RES_C_0603#1 648.65,2121.33 r180 top value=10k
R45 "Resistor" RES_C_0603#1 4265.06,2767.84 r0 bottom value=10k
R46 "Resistor" RES_C_0603#1 443.5,2820 r0 bottom value=2.2k
R47 "Resistor" RES_C_0603#1 3334.21,1957.68 r90 top value=8.2k
R48 "Resistor" RES_C_0603#1 3277.98,1958.86 r90 top value=20k
R49 "Resistor" RES_C_0603#1 1679.05,2649.73 r180 top value=0R
R50 "Resistor" RES_C_0603#1 1681.8,2714.67 r180 top value=10k
R51 "Resistor" RES_C_0603#1 1797.97,2714.67 r180 top value=0R
R52 "Resistor" RES_C_0603#1 1921.05,2714.67 r0 top value=10k
R53 "Resistor" RES_C_0603#1 3557.07,2107.03 r90 top value=100k
R54 "Resistor" RES_C_0603#1 1056.65,2924.73 r90 top value=49.9k
R55 "Resistor" RES_C_0603#1 3277.98,2072.16 r270 top value=750R
R56 "Resistor" RES_C_0603#1 1056.65,3038.91 r270 top value=43k
R57 "Resistor" RES_C_0603#1 443.5,3222.13 r90 top value=330R
R58 "Resistor" RES_C_0603#1 1280.35,3194.68 r180 top value=2.2k
R59 "Resistor" RES_C_0603#1 1622.74,3197.47 r180 top value=2.2k
R60 "Resistor" RES_C_0603#1 2449.15,3210 r180 top value=1k
R61 "Resistor" RES_C_0603#1 4211.28,-65 r180 bottom value=2.2k
R62 "Resistor" RES_C_0603#1 2004.15,105 r90 bottom value=330R
R63 "Resistor" RES_C_0603#1 1423.71,105 r270 bottom value=330R
R64 "Resistor" RES_C_0603#1 3957.22,155 r0 bottom value=330R
R65 "Resistor" RES_C_0603#1 124.15,160.9 r180 bottom value=330R
R66 "Resistor" RES_C_0603#1 2886.37,225.17 r180 bottom value=1k
R67 "0R" RES_C_0603#1 183.65,354.72 r270 bottom
R68 "0R" RES_C_0603#1 1599.46,492.7 r270 bottom
R69 "Resistor" RES_C_0603#1 1684.14,514.58 r180 bottom value=2R
R70 "Resistor" RES_C_0603#1 1514.85,514.58 r0 bottom value=2R
R71 "100k" RES_C_0603#1 1034.68,563.44 r270 bottom
R72 "100k" RES_C_0603#1 917.56,563.44 r270 bottom
R73 "Resistor" RES_C_0603#1 412.81,524.83 r180 bottom value=2R
R74 "Resistor" RES_C_0603#1 264.15,524.54 r180 bottom value=2R
R75 "Resistor" RES_C_0603#1 1145.2,691.52 r0 bottom value=49.9k
R76 "Resistor" RES_C_0603#1 703.65,728.55 r270 bottom value=43k
R77 "Resistor" RES_C_0603#1 644.91,728.57 r270 bottom value=560R
R78 "Resistor" RES_C_0603#1 1703.03,750.41 r0 bottom value=1k
R79 "Resistor" RES_C_0603#1 1465.17,737.54 r180 bottom value=1k
R80 "Resistor" RES_C_0603#1 1146.38,750.16 r180 bottom value=43k
R81 "Resistor" RES_C_0603#2 1029.19,750.16 r0 bottom value=560R
R82 "Resistor" RES_C_0603#1 881.38,750.16 r180 bottom value=49.9k
R83 "Resistor" RES_C_0603#1 490.9,744.31 r0 bottom value=1k
R84 "Resistor" RES_C_0603#1 218.47,744.31 r180 bottom value=1k
R85 "" RES_C_0603#1 580.95,872.39 r90 bottom value=100k
R86 "Resistor" RES_C_0603#1 1699.88,899.39 r180 bottom value=1k
R87 "Resistor" RES_C_0603#1 1468.39,899.39 r0 bottom value=1k
R88 "Resistor" RES_C_0603#1 486.86,898.31 r180 bottom value=1k
R89 "Resistor" RES_C_0603#1 218.47,898.31 r0 bottom value=1k
R90 "" RES_C_0603#1 1612.48,1009.86 r90 bottom value=100k
R91 "" RES_C_0603#1 1403.43,1009.86 r90 bottom value=100k
R92 "" RES_C_0603#1 855.94,973.67 r0 bottom value=100k
R93 "" RES_C_0603#1 407.44,994.74 r90 bottom value=100k
R94 "" RES_C_0603#1 345.15,994.74 r90 bottom value=100k
R95 "Resistor" RES_C_0603#1 2215,1381.04 r90 bottom value=10k
R96 "Resistor" RES_C_0603#1 -7.55,1719.53 r90 bottom value=200k
R97 "Resistor" RES_C_0603#1 2214.15,1490 r270 bottom value=10k
R98 "Resistor" RES_C_0603#1 -3.84,1558.02 r270 bottom value=200k
R99 "Resistor" RES_C_0603#1 2215,1950 r90 bottom value=10k
R100 "Resistor" RES_C_0603#1 2215,2050 r270 bottom value=10k
R101 "Resistor" RES_C_0603#1 3220.84,2072.16 r270 top value=2.55k
R102 "Resistor" RES_C_0603#1 4251.28,3220 r90 bottom value=330R
R103 "Resistor" RES_C_0603#1 3221.78,2187.42 r270 top value=0R
R104 "Resistor" RES_C_0603#1 3860.8,3031.89 r270 bottom value=20R
R105 "Resistor" RES_C_0603#1 443.5,2730 r0 bottom value=1k
R106 "Resistor" RES_C_0603#1 213.88,2570 r180 top value=10k
R107 "Resistor" RES_C_0603#1 1506.65,2694.73 r270 bottom value=10R
R108 "Resistor" RES_C_0603#1 1154.3,2694.73 r270 bottom value=10R
R109 "Resistor" RES_C_0603#1 205.31,2926.12 r0 top value=86.6k
R110 "Resistor" RES_C_0603#1 86.48,2928.32 r0 top value=12k
R111 "Resistor" RES_C_0603#1 102.23,2068 r270 bottom value=10k
R112 "Resistor" RES_C_0603#1 -26.17,2151.97 r0 top value=10k
R113 "Resistor" RES_C_0603#1 1506.65,2833.87 r90 bottom value=200k
R114 "Resistor" RES_C_0603#1 1156.06,2833.87 r90 bottom value=200k
R115 "Resistor" RES_C_0603#1 1950.58,2843.98 r0 bottom value=100k
R116 "Resistor" RES_C_0603#1 335.5,2570 r180 bottom value=500R
R117 "Resistor" RES_C_0603#1 1644.64,2879.73 r180 bottom value=100k
R118 "Resistor" RES_C_0603#1 1646.47,2943.98 r0 bottom value=10k
R119 "Resistor" RES_C_0603#1 -111.77,2185.97 r270 top value=12k
R120 "Resistor" RES_C_0603#1 2239.15,3081.72 r270 bottom value=100k
R121 "Resistor" RES_C_0603#1 2134.47,3083.54 r270 bottom value=300R
R122 "Resistor" RES_C_0603#1 -111.77,2075.97 r90 top value=10k
R124 "Resistor" RES_C_0603#2 6.64,1220 r270 bottom value=10k
R125 "Resistor" RES_C_0603#2 7.55,1360 r270 bottom value=10k
SW1 "Switch 6 Pin DPDT" SW_SLIDE_SMD_JS202011SCQN 4385.34,2668.38 r180 top value=JS202011SCQN
SW2 "Switch 4 Pin" SW_TACT_SMD_CK_PTS810SJM 2199.15,3222.28 r180 top value=SPST-NO
TP1 "Test Point" CON_TP_TH_V_RED_KEC_5000 3467.61,2961.42 r180 top value=Red
TP2 "Test Point" CON_TP_TH_V_BLK_KEC_5001 -60.78,2456.98 r270 top value="TP LOOP Black"
TP3 "Test Point" CON_TP_TH_V_ORN_KEC_5003 142.18,2456.34 r270 top value="TP LOOP Orange"
TP4 "Test Point No BOM" CON_TP_22P11_TH 674.18,2066.78 r90 top value="TP PAD .56mm"
TP5 "Test Point" CON_TP_TH_V_YEL_KEC_5004 195.68,1878.42 r0 top value="TP LOOP Yellow"
TP6 "Test Point" CON_TP_TH_V_BLK_KEC_5001 3135.15,2735 r0 top value=Black
TP7 "Test Point" CON_TP_TH_V_RED_KEC_5000 2612.18,1775 r0 top value="TP LOOP Red"
TP8 "Test Point" CON_TP_TH_V_BLK_KEC_5001 2612.18,1582.79 r0 top value=Black
U1 "UCS2114 VQFN-20" QFN-20_3X3_P0.5_EP0_UCS2114 974.64,492.69 r0 top value=UCS2114-1A
U2 "UCS2114 VQFN-20" QFN-20_3X3_P0.5_EP0_UCS2114 3126.65,665 r0 top value=UCS2114-1A
U3 "USB7252 VQFN-100" TQFN-100_12x12_EP8.0 924.18,1619.13 r0 top value=USB7252
U4 "MCP19035 DFN-10" DFN-10_3x3 3453.7,2141.06 r90 top locked value=MCP19035
U5 "MCP111_2 SOT-23-3_SC-70-3" SOT-23-3 3665.84,2131.21 r0 top value=MCP111/4.6V
U6 "MIC23201 MLF-10" MLF-10_3x3_1.6X2.5 -3.4,2018.97 r270 top value=MIC23201
U7 "MCP1825T_ADJE SOT-223" SOT-223-5 17.56,2750.34 r90 top value=MCP1825/ADJ
U8 "SST26VFXXX SOIC-8_WSON-8_SOIJ-8" SOIJ-8 1822.75,2868.98 r0 top value=SST26VF016B
U9 "74LVC1G14GW,125" SC-70-5 1641.65,3109.13 r270 top
U10 "MIC803 SOT-23-3" SOT-23-3 2380.77,2974.72 r0 bottom value=MIC803/2.93V
U11 "74LVC1G14GW,125" SC-70-5 2343.37,3104.41 r90 bottom
Y1 "OSCILLATOR_4P_nSTBY" OSCILLATOR_CDFN_L2.5W2.0H0.85 513.95,2039.73 r270 top value=25MHz

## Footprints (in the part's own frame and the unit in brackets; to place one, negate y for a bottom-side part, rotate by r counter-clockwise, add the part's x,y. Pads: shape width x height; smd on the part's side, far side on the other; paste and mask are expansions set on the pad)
CAP_AL_D8 [mm]
  rect 3.5x0.75 smd: 1(-2.55,0) 2(2.55,0)
  silkscreen extent -3.43,-3.3 3.43,3.3, body extent -3.5,-3.3 3.5,3.3, height 7.7
CAP_AL_F [mm]
  rect 4.3x1 smd: 1(-3,0) 2(3,0)
  silkscreen extent -4.5,-4.15 4.5,4.15, body extent -4.9,-4.15 5,4.15, height 10.2
CAP_C_0402#1 [mm] "Chip Capacitor 2-Leads, Body 1.6x0.8mm, IPC Medium Density"
  rrect50% 0.5x0.56 smd: 1(-0.53,0) 2(0.53,0)
  silkscreen extent -0.1,-0.38 0.1,0.38, body extent -0.5,-0.25 0.5,0.25, height 0.49
CAP_C_0402#2 [mm] "Chip Capacitor, 2-Leads, Body 1.0x0.5mm, IPC High Density"
  rrect50% 0.55x0.6 smd: 1(-0.45,0) 2(0.45,0)
  body extent -0.5,-0.3 0.5,0.3, height 0.2
CAP_C_0603 [mm] "Chip Capacitor 2-Leads, Body 1.6x0.8mm, IPC Medium Density"
  rrect50% 0.7x0.8 smd: 1(-0.75,0) 2(0.75,0)
  silkscreen extent -0.29,-0.58 0.3,0.58, body extent -0.8,-0.4 0.8,0.4, height 0.79
CAP_C_0805 [mm] "Chip Capacitor, 2-Leads, Body 2.0x1.3mm, IPC Medium Density"
  rrect50% 0.8x1.3 smd: 1(-0.9,0) 2(0.9,0)
  silkscreen extent -0.2,-0.7 0.2,0.7, body extent -1,-0.62 1,0.63, height 0.78
CAP_C_1206 [mm] "Chip Capacitor, 2-Leads, Body 3.2x1.6mm, IPC Medium Density"
  rrect50% 1x1.75 smd: 1(-1.5,0) 2(1.5,0)
  silkscreen extent -0.6,-0.77 0.6,0.77, body extent -1.6,-0.8 1.6,0.8, height 1
CAP_C_1210 [mm] "Chip Capacitor, 2-Leads, Body 3.2x2.5mm, IPC Medium Density"
  rect 1x2.6 smd: 1(-1.5,0) 2(1.5,0)
  silkscreen extent -0.6,-1.2 0.6,1.2, body extent -1.6,-1.25 1.6,1.25, height 0.95
CON_HDR_2.54_3X2 [mil] "Header Male Vertical Dual Row 3 Way 2.54mm Pitch"
  oct 51x51 hole 36: 1(-50,-100)
  round 51 hole 36: 2(-50,0) 3(-50,100) 4(50,-100) 5(50,0) 6(50,100)
  silkscreen extent -108,-157 108,157, body extent -100,-150 100,150, height 330
CON_JACK_POWER_TH_RA_CUI_PJ-063BH [mm] "Connector, Power Jack, 2.5mm x 6.5mm, 16V, 8A, Right Angle, TH"
  oval 3.516x2.54 hole 1.524 slot 2.5 at 0 deg: 0(2.5,4.677) 0(2.5,-4.677)
  oval 2.54x4 hole 1.524 slot 3 at 90 deg: 1(-4.5,0)
  oval 2.54x3.316 hole 1.524 slot 2.3 at 90 deg: 2(1.5,0)
  round 2.6 hole 1.663: ""(4.5,0)
  silkscreen extent -5.79,-5.46 7.77,5.46, body extent -5.51,-5.12 7.49,5.17, height 10
CON_TERMINAL_5.08_1x2_TH_RA_OST_OSTOQ025451 [mm] "TERMINAL BLOCK 5.08MM 2POS PCB RA"
  round 2.6 hole 1.6: 1(-2.54,0) 2(2.54,0)
  silkscreen extent -6.35,-10.15 6.35,2.29, body extent -6.1,-10 6.06,2, height 8.5
CON_TP_22P11_TH [mil]
  oval 22x22.05 hole 11 paste-22.05 mask+2: 1(0,0)
  silkscreen extent -18,-18 18,18
CON_TP_TH_V_BLK_KEC_5001 [mil] "TEST POINT PC MULTI PURPOSE MINI BLACK"
  round 56 hole 36: 1(0,0)
  silkscreen extent -50,-50 50,50, body extent -50,-50 50,50, height 192
CON_TP_TH_V_ORN_KEC_5003 [mm] "TEST POINT PC MULTI PURPOSE MINI ORN"
  round 2 hole 1: 1(0,0)
  silkscreen extent -1.27,-1.27 1.27,1.27, body extent -1.27,-1.27 1.27,1.27, height 4.89
CON_TP_TH_V_RED_KEC_5000 [mil] "TEST POINT PC MULTI PURPOSE MINI RED"
  round 56 hole 36: 1(0,0)
  silkscreen extent -50,-50 50,50, body extent -50,-50 50,50, height 192
CON_TP_TH_V_YEL_KEC_5004 [mm] "TEST POINT PC MULTI PURPOSE MINI YEL"
  round 2 hole 1: 1(0,0)
  silkscreen extent -1.27,-1.27 1.27,1.27, body extent -1.27,-1.27 1.27,1.27, height 4.89
CON_USB2.0-A_TH_RA_FCI_87520-0010BLF [mm] "CONN USB 2.0 A RCPT TH R/A L=14mm, W=13.1mm, H=7mm"
  round 3.5 hole 2.3: 0(-6.57,0) 0(6.57,0)
  rrect50% 1.5x2.3 hole 1: 1(-3.5,2.565) 4(3.5,2.565)
  rect 1.5x2.3 hole 1: 2(-1,2.565) 3(1,2.565)
  silkscreen extent -7,-9.75 7,4.13, body extent -7.9,-10.3 7.9,3.4, height 6.95
CON_USB3.0-A_RCPT_TH_RA_WE_692121030100 [mm]
  round 3.3 hole 2.3: 0(-6.57,0) 0(6.57,0)
  round 1.1 hole 0.7: 1(-3.5,2) 2(-1,2) 3(1,2) 4(3.5,2) 5(4,3.5) 6(2,3.5) 7(0,3.5) 8(-2,3.5) 9(-4,3.5)
  silkscreen extent -8.6,-6.1 8.6,4.9, body extent -7.74,-11.78 7.74,4.7, height 8.06
CON_USB3.0-B_RCPT_SMD_RA_HIR_ZX360D-B-10P [mm] "CONN RCPT USB 3.0 MICRO B SMD, L=12.85mm, W=5.0mm, H=2.5mm"
  oval 0.9x1.8 hole 0.5 slot 1.4 at 90 deg: 0(-5.935,0.25) 0(6.665,0.25)
  rect 1.9x1.9 smd: 0(-3.515,0.25) 0(-1.115,0.25)
  rect 2.3x1.9 smd: 0(1.435,0.25)
  rect 1.8x1.9 smd: 0(4.235,0.25)
  rrect50% 0.4x1.35 smd: 1(-3.615,2.925) 2(-2.965,2.925) 3(-2.315,2.925) 4(-1.665,2.925) 5(-1.015,2.925) 6(3.085,2.925) 7(3.735,2.925) 8(4.385,2.925) 9(5.035,2.925) 10(5.685,2.925)
  silkscreen extent -6.26,-1.2 6.99,3.58, body extent -6.42,-2.5 7.15,3.1, height 2.83
CON_USB3.1-C_RCPT_SMD_RA_ACP_12401610E4#2A [mm] "USB TYPE-C, RA RCPT, SMT"
  round 0.65 hole 0.65 unplated paste-0.325: 0(-3.6,4.34)
  oval 0.95x0.65 hole 0.65 slot 0.95 at 0 deg unplated paste-0.325: 0(3.6,4.34)
  oval 0.8x1.4 hole 0.5 slot 1.1 at 90 deg paste-1.4 mask+0: 25(-4.49,-2.86) 25(-4.13,3.09) 25(4.13,3.09) 25(4.49,-2.86)
  rect 0.3x0.7 smd mask+0: A1(-2.75,5) A2(-2.25,5) A3(-1.75,5) A4(-1.25,5) A5(-0.75,5) A6(-0.25,5) A7(0.25,5) A8(0.75,5) A9(1.25,5) A10(1.75,5) A11(2.25,5) A12(2.75,5) B1(2.5,3.3) B2(2,3.3) B3(1.5,3.3) B4(1,3.3) B5(0.5,3.3) B6(0,3.3) B7(-0.5,3.3) B8(-1,3.3) B9(-1.5,3.3) B10(-2,3.3) B11(-2.5,3.3) B12(-3,3.3)
  silkscreen extent -4.76,-1.86 4.77,5.41, body extent -4.6,-5.27 4.6,5.23, height 3.01
DFN-10_3x3 [mm] "DFN, 10-Leads, Body 3.0x3.0mm (max), Pitch 0.50mm, IPC Medium Density"
  rect 0.8x0.3 smd paste-0.038 mask+0.05: 1(-1.55,1) 2(-1.55,0.5) 3(-1.55,0) 4(-1.55,-0.5) 5(-1.55,-1) 6(1.55,-1) 7(1.55,-0.5) 8(1.55,0) 9(1.55,0.5) 10(1.55,1)
  rect 1.65x2.38 smd paste-0.305: 11(0,0)
  silkscreen extent -1.6,-1.6 1.6,1.6, body extent -1.56,-1.55 1.56,1.55, height 0.8
DO-214AC_SMA [mm] "Molded Diode, 2-Leads, Body 5.0x2.7mm, IPC Medium Density"
  rect 2.5x1.7 smd: 1(-2,0) 2(2,0)
  silkscreen extent -2.7,-1.5 2.7,1.5, body extent -2.6,-1.3 2.6,1.3, height 2.4
FIDUCIAL [mil]
  round 40 smd mask+20: 1(0,0)
  Top Layer pour cut-out: 40.35,0 38.97,10.44 34.94,20.17 28.53,28.53 20.17,34.94 10.44,38.97 0,40.35 0,40.35 -10.44,38.97 -20.17,34.94 -28.53,28.53 -34.94,20.17 -38.97,10.44 -40.35,0 -40.35,0 -38.97,-10.44 -34.94,-20.17 -28.53,-28.53 -20.17,-34.94 -10.44,-38.97 0,-40.35 0,-40.35 10.44,-38.97 20.17,-34.94 28.53,-28.53 34.94,-20.17 38.97,-10.44 40.35,0
  body extent -40,-40 40,40, height 0
FUSEHOLDER_LITTLEFUSE_155900 [mm] "FUSE BRD MNT WITH HOLDER LITTLEFUSE-154 SMD"
  rect 4.24x3.81 smd: 1(-3.19,0) 2(3.19,0)
  silkscreen extent -5.2,-2.7 5.2,2.7, body extent -4.86,-2.5 4.84,2.5, height 3.69
HDR_M_2.54_1x1 [mm] "Header Male Vertical 1 Way"
  oct 1.7x1.7 hole 0.9: 1(0,0)
  silkscreen extent -1.27,-1.27 1.27,1.27, body extent -1.27,-1.27 1.27,1.27, height 5.94
HDR_M_2.54_1x2 [mm] "Header Male Vertical 4 Way 2.54mm Pitch"
  oct 1.7x1.7 hole 0.9: 1(-1.27,0)
  round 1.7 hole 0.9: 2(1.27,0)
  silkscreen extent -2.6,-1.35 2.6,1.4, body extent -2.54,-1.27 2.54,1.27, height 5.94
HDR_M_2.54_1x3 [mm] "Header Male Vertical 4 Way P=2.54mm"
  oct 1.7x1.7 hole 0.9: 1(-2.54,0)
  round 1.7 hole 0.9: 2(0,0) 3(2.54,0)
  silkscreen extent -3.94,-1.4 3.96,1.4, body extent -3.8,-1.26 3.82,1.28, height 5.94
HDR_M_2.54_1x6 [mm] "Header Male Vertical 6 Way 2.54mm Pitch"
  oct 1.7x1.7 hole 0.9: 1(-6.35,0)
  round 1.7 hole 0.9: 2(-3.81,0) 3(-1.27,0) 4(1.27,0) 5(3.81,0) 6(6.35,0)
  silkscreen extent -7.75,-1.4 7.7,1.4, body extent -7.62,-1.27 7.62,1.27, height 8.38
HDR_M_2.54_2x2#1 [mil] "Header Male Vertical 2x2 Way 2.54mm Pitch"
  oct 65x65 hole 35.43: 1(-50,-50)
  round 65 hole 35.43: 2(-50,50) 3(50,-50) 4(50,50)
  silkscreen extent -102,-102 102,102, body extent -100,-100 100,100, height 234
HDR_M_2.54_2x2#2 [mil] "Header Male Vertical 2x2 Way 2.54mm Pitch"
  oct 66.93x66.93 hole 35.43: 1(-50,-50)
  round 66.93 hole 35.43: 2(-50,50) 3(50,-50) 4(50,50)
  silkscreen extent -102,-102 102,102, body extent -100,-100 100,100, height 234
IND_MUR_LQH5B_L5W5H2 [mm] "Chip Inductor 2-Leads, Body 5.0mmx5.0mm, IPC Medium Density"
  rect 1.9x4.1 smd: 1(-1.85,0) 2(1.85,0)
  silkscreen extent -2.8,-2.8 2.8,2.8, body extent -2.51,-2.5 2.49,2.5, height 2
IND_WE_7443551200_L12.8W12.8H6.2 [mm] "Chip Inductor 2-Leads, Body 12.8mm sq, IPC Medium Density"
  rect 4.5x4 smd: 1(-5.25,0) 2(5.25,0)
  silkscreen extent -7.3,-6.6 7.3,6.6, body extent -7.1,-6.4 7.1,6.4, height 6.44
LABEL_Need_Help_Small [mil] "Small Serial Number Assembly Label"
  silkscreen extent -450,-125 450,125, body extent -450,-125 450,125, height 12
LED_0603_BLUE [mm] "LED chip 0603 - BLUE"
  rrect50% 0.7x0.8 smd: 1(-0.75,0) 2(0.75,0)
  silkscreen extent -0.28,-0.58 1.3,0.58, body extent -0.81,-0.4 0.81,0.4, height 0.6
LED_0603_GREEN [mm] "LED chip 0603 - GREEN"
  rrect50% 0.7x0.8 smd: 1(-0.75,0) 2(0.75,0)
  silkscreen extent -0.3,-0.58 1.3,0.58, body extent -0.81,-0.4 0.81,0.4, height 0.6
LED_0603_RED [mm] "LED chip 0603 - RED"
  rrect50% 0.7x0.8 smd: 1(-0.75,0) 2(0.75,0)
  silkscreen extent -0.33,-0.58 1.3,0.58, body extent -0.81,-0.4 0.81,0.4, height 0.6
MLF-10_3x3_1.6X2.5 [mm] "MLF 10-Leads, Body 3.0x3.0mm (max), Pitch 0.50mm, IPC Medium Density"
  rrect15% 0.6x0.25 smd mask+0.064: 1(-1.42,1) 2(-1.42,0.5) 3(-1.42,0) 4(-1.42,-0.5) 5(-1.42,-1) 6(1.42,-1) 7(1.42,-0.5) 8(1.42,0) 9(1.42,0.5) 10(1.43,1)
  rrect20% 1.6x2.5 smd mask+0.064: 11(0,0)
  body extent -1.56,-1.55 1.56,1.55, height 0.8
MTHOLE_4-40#1 [mil]
  round 220 hole 120: 1(0,0)
  body extent -110,-110 110,110, height 0
MTHOLE_4-40#2 [mil]
  round 220 hole 120: 1(5.85,0)
  body extent -110,-110 110,110, height 0
OSCILLATOR_CDFN_L2.5W2.0H0.85 [mm] "CDFN-4 L2.5W2.0H0.85"
  rect 0.9x1 smd: 1(-1.05,-0.95) 2(1.05,-0.95) 3(1.05,0.95) 4(-1.05,0.95)
  silkscreen extent -1.75,-1.5 1.75,1.5, body extent -1.6,-1.25 1.6,1.25, height 0.86
PG-TDSON-8_4.7x6.5 [mm] "TDSON-8 package 4.7x6.85 body , 8 pin"
  rect 0.65x1.2 smd: 1(-1.905,-2.825) 2(-0.635,-2.825) 3(0.635,-2.825) 4(1.905,-2.825)
  rect 0.7x1 smd: 5(2,2.925) 6(0.665,2.925) 7(-0.665,2.925) 8(-2,2.925)
  Top Layer region: -2.35,2.925 2.35,2.925 2.35,-1.575 -2.35,-1.575
  silkscreen extent -2.7,-3.2 2.7,3.2, body extent -2.79,-3.1 2.8,3.25, height 1.1
Power56-8_5x6 [mm] "Power56 package 5x6 body , 8 pin"
  rect 0.61x1.27 smd: 1(-1.905,-2.67) 2(-0.635,-2.67) 3(0.635,-2.67) 4(1.905,-2.67)
  rect 0.61x1.02 smd: 5(1.905,2.795) 6(0.635,2.795) 7(-0.635,2.795) 8(-1.905,2.795)
  Top Layer region: -1.955,-1.22 1.955,-1.22 1.955,2.54 -1.955,2.54
  silkscreen extent -2.7,-3.2 2.7,3.2, body extent -2.57,-3 2.58,3.15, height 1.04
QFN-20_3X3_P0.5_EP0_UCS2114 [mm] "QFN-20_3X3 Pitch 0.5mm for UCS2114"
  rect 0.45x0.25 smd mask+0.064: 1(-1.625,1) 5(-1.625,-1) 11(1.625,-1) 15(1.625,1)
  rect 0.65x0.25 smd mask+0.064: 2(-1.525,0.5) 3(-1.525,0) 4(-1.525,-0.5) 12(1.525,-0.5) 13(1.525,0) 14(1.525,0.5)
  rect 0.25x0.45 smd mask+0.064: 6(-1,-1.625) 10(1,-1.625) 16(1,1.625) 20(-1,1.625)
  rect 0.25x0.65 smd mask+0.064: 7(-0.5,-1.525) 8(0,-1.525) 9(0.5,-1.525) 17(0.5,1.525) 18(0,1.525) 19(-0.5,1.525)
  Top Layer pour cut-out: -1,1 1,1 1,-1 -1,-1
  Top Layer region: 0.375,1.275 0.375,0.975 -0.975,0.975 -0.975,-0.175 0.975,-0.175 0.975,0.975 0.625,0.975 0.625,1.275
  Top Layer region: -1.125,1.3 -1.025,1.2 -0.875,1.2 -0.875,1.45 -1.125,1.45
  Top Layer region: 1.125,1.3 1.025,1.2 0.875,1.2 0.875,1.45 1.125,1.45
  Top Layer region: 1.3,1.125 1.2,1.025 1.2,0.875 1.45,0.875 1.45,1.125
  Top Layer region: -1.3,1.125 -1.2,1.025 -1.2,0.875 -1.45,0.875 -1.45,1.125
  Top Layer region: -1.315,-1.125 -1.2,-1.01 -1.2,-0.875 -1.45,-0.875 -1.45,-1.125
  Top Layer region: -1.125,-1.29 -1.035,-1.2 -0.875,-1.2 -0.875,-1.45 -1.125,-1.45
  Top Layer region: 1.315,-1.125 1.2,-1.01 1.2,-0.875 1.45,-0.875 1.45,-1.125
  Top Layer region: 1.125,-1.29 1.035,-1.2 0.875,-1.2 0.875,-1.45 1.125,-1.45
  silkscreen extent -1.7,-1.7 1.7,1.7, body extent -1.55,-1.55 1.55,1.55, height 0.85
RES_C_0603#1 [mm] "Chip Resistor, 2-Leads, Body 1.6x0.8mm, IPC Medium Density"
  rrect50% 0.7x0.8 smd: 1(-0.75,0) 2(0.75,0)
  silkscreen extent -0.26,-0.56 0.21,0.56, body extent -0.8,-0.4 0.8,0.4, height 0.45
RES_C_0603#2 [mm] "Chip Resistor, 2-Leads, Body 1.6x0.8mm, IPC Medium Density"
  rrect50% 0.8x0.9 smd: 1(-0.8,0) 2(0.8,0)
  silkscreen extent -0.1,-0.38 0.1,0.38, body extent -0.8,-0.4 0.8,0.4, height 0.3
SC-70-5 [mm]
  rect 0.45x0.95 smd mask+0.05: 1(-0.65,-1.1) 2(0,-1.1) 3(0.65,-1.1) 4(0.65,1.1) 5(-0.65,1.1)
  silkscreen extent -1.1,-0.33 1.1,0.33, body extent -1,-1.05 1,1.05, height 0.95
SC-88-6 [mm]
  rect 0.4x0.5 smd: 1(-0.65,-0.95) 2(0,-0.95) 3(0.65,-0.95) 4(0.65,0.95) 5(0,0.95) 6(-0.65,0.95)
  silkscreen extent -1,-0.33 1,0.33, body extent -1,-1.1 1,1.1, height 1.1
SOCKET_I2S_F_2.54_2x8_V_25.4x21_SMD [mm] "I2S Daughter Card connector, SMD, Standard (right) bend"
  rrect50% 2x1 smd mask+0.076: 1(-11.049,8.89) 2(-14.351,6.35) 3(-11.049,3.81) 4(-14.351,1.27) 5(-11.049,-1.27) 6(-14.351,-3.81) 7(-11.049,-6.35) 8(-14.351,-8.89) 9(11.049,-8.89) 10(14.351,-6.35) 11(11.049,-3.81) 12(14.351,-1.27) 13(11.049,1.27) 14(14.351,3.81) 15(11.049,6.35) 16(14.351,8.89)
  silkscreen extent -15.24,-11.43 15.24,12.06, body extent -14.8,-10.36 14.8,10.36, height 7.46
SOD-323 [mm] "Molded Diode, 2-Leads, Body 1.8x1.4mm, IPC Medium Density"
  rect 0.63x0.83 smd: 1(-1.115,0) 2(1.115,0)
  silkscreen extent -0.17,-0.7 1.73,0.32, body extent -1.3,-0.68 1.3,0.67, height 1.1
SOIJ-8 [mm] "SOIC, 8-Leads, Overall 4.9x6mm, Pitch 1.27mm, IPC Medium Density"
  oval 1.55x0.6 smd: 1(-3.65,1.905) 2(-3.65,0.635) 3(-3.65,-0.635) 4(-3.65,-1.905) 5(3.65,-1.905) 6(3.65,-0.635) 7(3.65,0.635) 8(3.65,1.905)
  silkscreen extent -2.5,-2.8 2.5,2.8, body extent -4.05,-2.73 4.05,2.73, height 1.75
SOT-23-3 [mm]
  rect 0.65x1.05 smd: 1(-0.95,-1.15) 2(0.95,-1.15) 3(0,1.15)
  silkscreen extent -1.6,-0.75 1.6,0.72, body extent -1.5,-1.25 1.5,1.25, height 1.09
SOT-23-3_REVERSED [mm]
  rect 0.65x1.05 smd: 1(0,1.15) 2(0.95,-1.15) 3(-0.95,-1.15)
  silkscreen extent -1.6,-0.75 1.6,0.72, body extent -1.5,-1.25 1.5,1.25, height 1.09
SOT-223-5 [mm] "SOT-223-5, 5-Leads + thermal connected to pin 3, Body 6.5x7.26mm (max), Pitch 1.27mm H=1.65mm"
  rect 0.65x2 smd: 1(-2.54,-3) 2(-1.27,-3) 3(0,-3) 4(1.27,-3) 5(2.54,-3)
  rect 3.2x2 smd: 6(0,3)
  body extent -3.27,-3.63 3.28,3.63, height 1.8
SW_SLIDE_SMD_JS202011SCQN [mm] "SWITCH SLIDE DPDT 6VDC 0.3A SMT"
  rect 2.5x1.2 smd: 1(-2.749,2.499) 2(-2.749,-0.001) 3(-2.749,-2.501) 4(2.751,2.499) 5(2.751,-0.001) 6(2.751,-2.501)
  silkscreen extent -2,-4.6 2,4.6, body extent -3.45,-4.53 3.45,4.52, height 5.45
SW_TACT_SMD_CK_PTS810SJM [mm]
  rect 1.2x0.65 smd: 1(-2.15,1.075) 2(2.15,1.075) 3(-2.15,-1.075) 4(2.15,-1.075)
  silkscreen extent -2.73,-1.92 2.78,1.97, body extent -2.37,-1.57 2.43,1.63, height 2.6
TQFN-100_12x12_EP8.0 [mm] "QFN, 100 pin, 12x12 body, 0.4mm pitch, EPAD 6.9mm, gang masked, windowed paste"
  oval 1.06x0.222 smd: 1(-5.82,4.8) 2(-5.82,4.4) 3(-5.82,4) 4(-5.82,3.6) 5(-5.82,3.2) 6(-5.82,2.8) 7(-5.82,2.4) 8(-5.82,2) 9(-5.82,1.6) 10(-5.82,1.2) 11(-5.82,0.8) 12(-5.82,0.4) 13(-5.82,0) 14(-5.82,-0.4) 15(-5.82,-0.8) 16(-5.82,-1.2) 17(-5.82,-1.6) 18(-5.82,-2) 19(-5.82,-2.4) 20(-5.82,-2.8) 21(-5.82,-3.2) 22(-5.82,-3.6) 23(-5.82,-4) 24(-5.82,-4.4) 25(-5.82,-4.8) 51(5.82,-4.8) 52(5.82,-4.4) 53(5.82,-4) 54(5.82,-3.6) 55(5.82,-3.2) 56(5.82,-2.8) 57(5.82,-2.4) 58(5.82,-2) 59(5.82,-1.6) 60(5.82,-1.2) 61(5.82,-0.8) 62(5.82,-0.4) 63(5.82,0) 64(5.82,0.4) 65(5.82,0.8) 66(5.82,1.2) 67(5.82,1.6) 68(5.82,2) 69(5.82,2.4) 70(5.82,2.8) 71(5.82,3.2) 72(5.82,3.6) 73(5.82,4) 74(5.82,4.4) 75(5.82,4.8)
  oval 0.222x1.06 smd: 26(-4.8,-5.82) 27(-4.4,-5.82) 28(-4,-5.82) 29(-3.6,-5.82) 30(-3.2,-5.82) 31(-2.8,-5.82) 32(-2.4,-5.82) 33(-2,-5.82) 34(-1.6,-5.82) 35(-1.2,-5.82) 36(-0.8,-5.82) 37(-0.4,-5.82) 38(0,-5.82) 39(0.4,-5.82) 40(0.8,-5.82) 41(1.2,-5.82) 42(1.6,-5.82) 43(2,-5.82) 44(2.4,-5.82) 45(2.8,-5.82) 46(3.2,-5.82) 47(3.6,-5.82) 48(4,-5.82) 49(4.4,-5.82) 50(4.8,-5.82) 76(4.8,5.82) 77(4.4,5.82) 78(4,5.82) 79(3.6,5.82) 80(3.2,5.82) 81(2.8,5.82) 82(2.4,5.82) 83(2,5.82) 84(1.6,5.82) 85(1.2,5.82) 86(0.8,5.82) 87(0.4,5.82) 88(0,5.82) 89(-0.4,5.82) 90(-0.8,5.82) 91(-1.2,5.82) 92(-1.6,5.82) 93(-2,5.82) 94(-2.4,5.82) 95(-2.8,5.82) 96(-3.2,5.82) 97(-3.6,5.82) 98(-4,5.82) 99(-4.4,5.82) 100(-4.8,5.82)
  rect 8.1x8.1 smd paste-5: 101(0,0)
  silkscreen extent -6.15,-6.15 6.15,6.15, body extent -6,-6 6,6, height 1.01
